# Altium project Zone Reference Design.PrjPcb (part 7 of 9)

## Sheet AM263P Overview.SchDoc
size 431 x 279 mm; Date: Not shown in title block; ApprovedBy: Not shown in title block; CheckedBy: Not shown in title block; Author: Not shown in title block; CompanyName: Not shown in title block; Engineer: Not shown in title block; Organization: Not shown in title block; Address1: Not shown in title block; Address2: Not shown in title block; Address3: Not shown in title block; Address4: Not shown in title block; DocumentNumber: 1; Revision: Use project parameter SCH_Rev; SheetNumber: 6; SheetTotal: 30; PageSetup: Record=PageOptions¦CenterHorizontal=True¦CenterVertical=True¦PrintScale=1.00¦XCorrection=1.00¦YCorrection=1.00¦PrintKind=0¦BorderSize=5000000¦LeftOffset=0¦BottomOffset=0¦Orientation=2¦PaperLength=1000¦PaperWidth=1000¦Scale=100¦PaperSource=15¦PrintQuality=600¦MediaType=1¦DitherType=10¦PaperKind=Letter¦PrintScaleMode=1
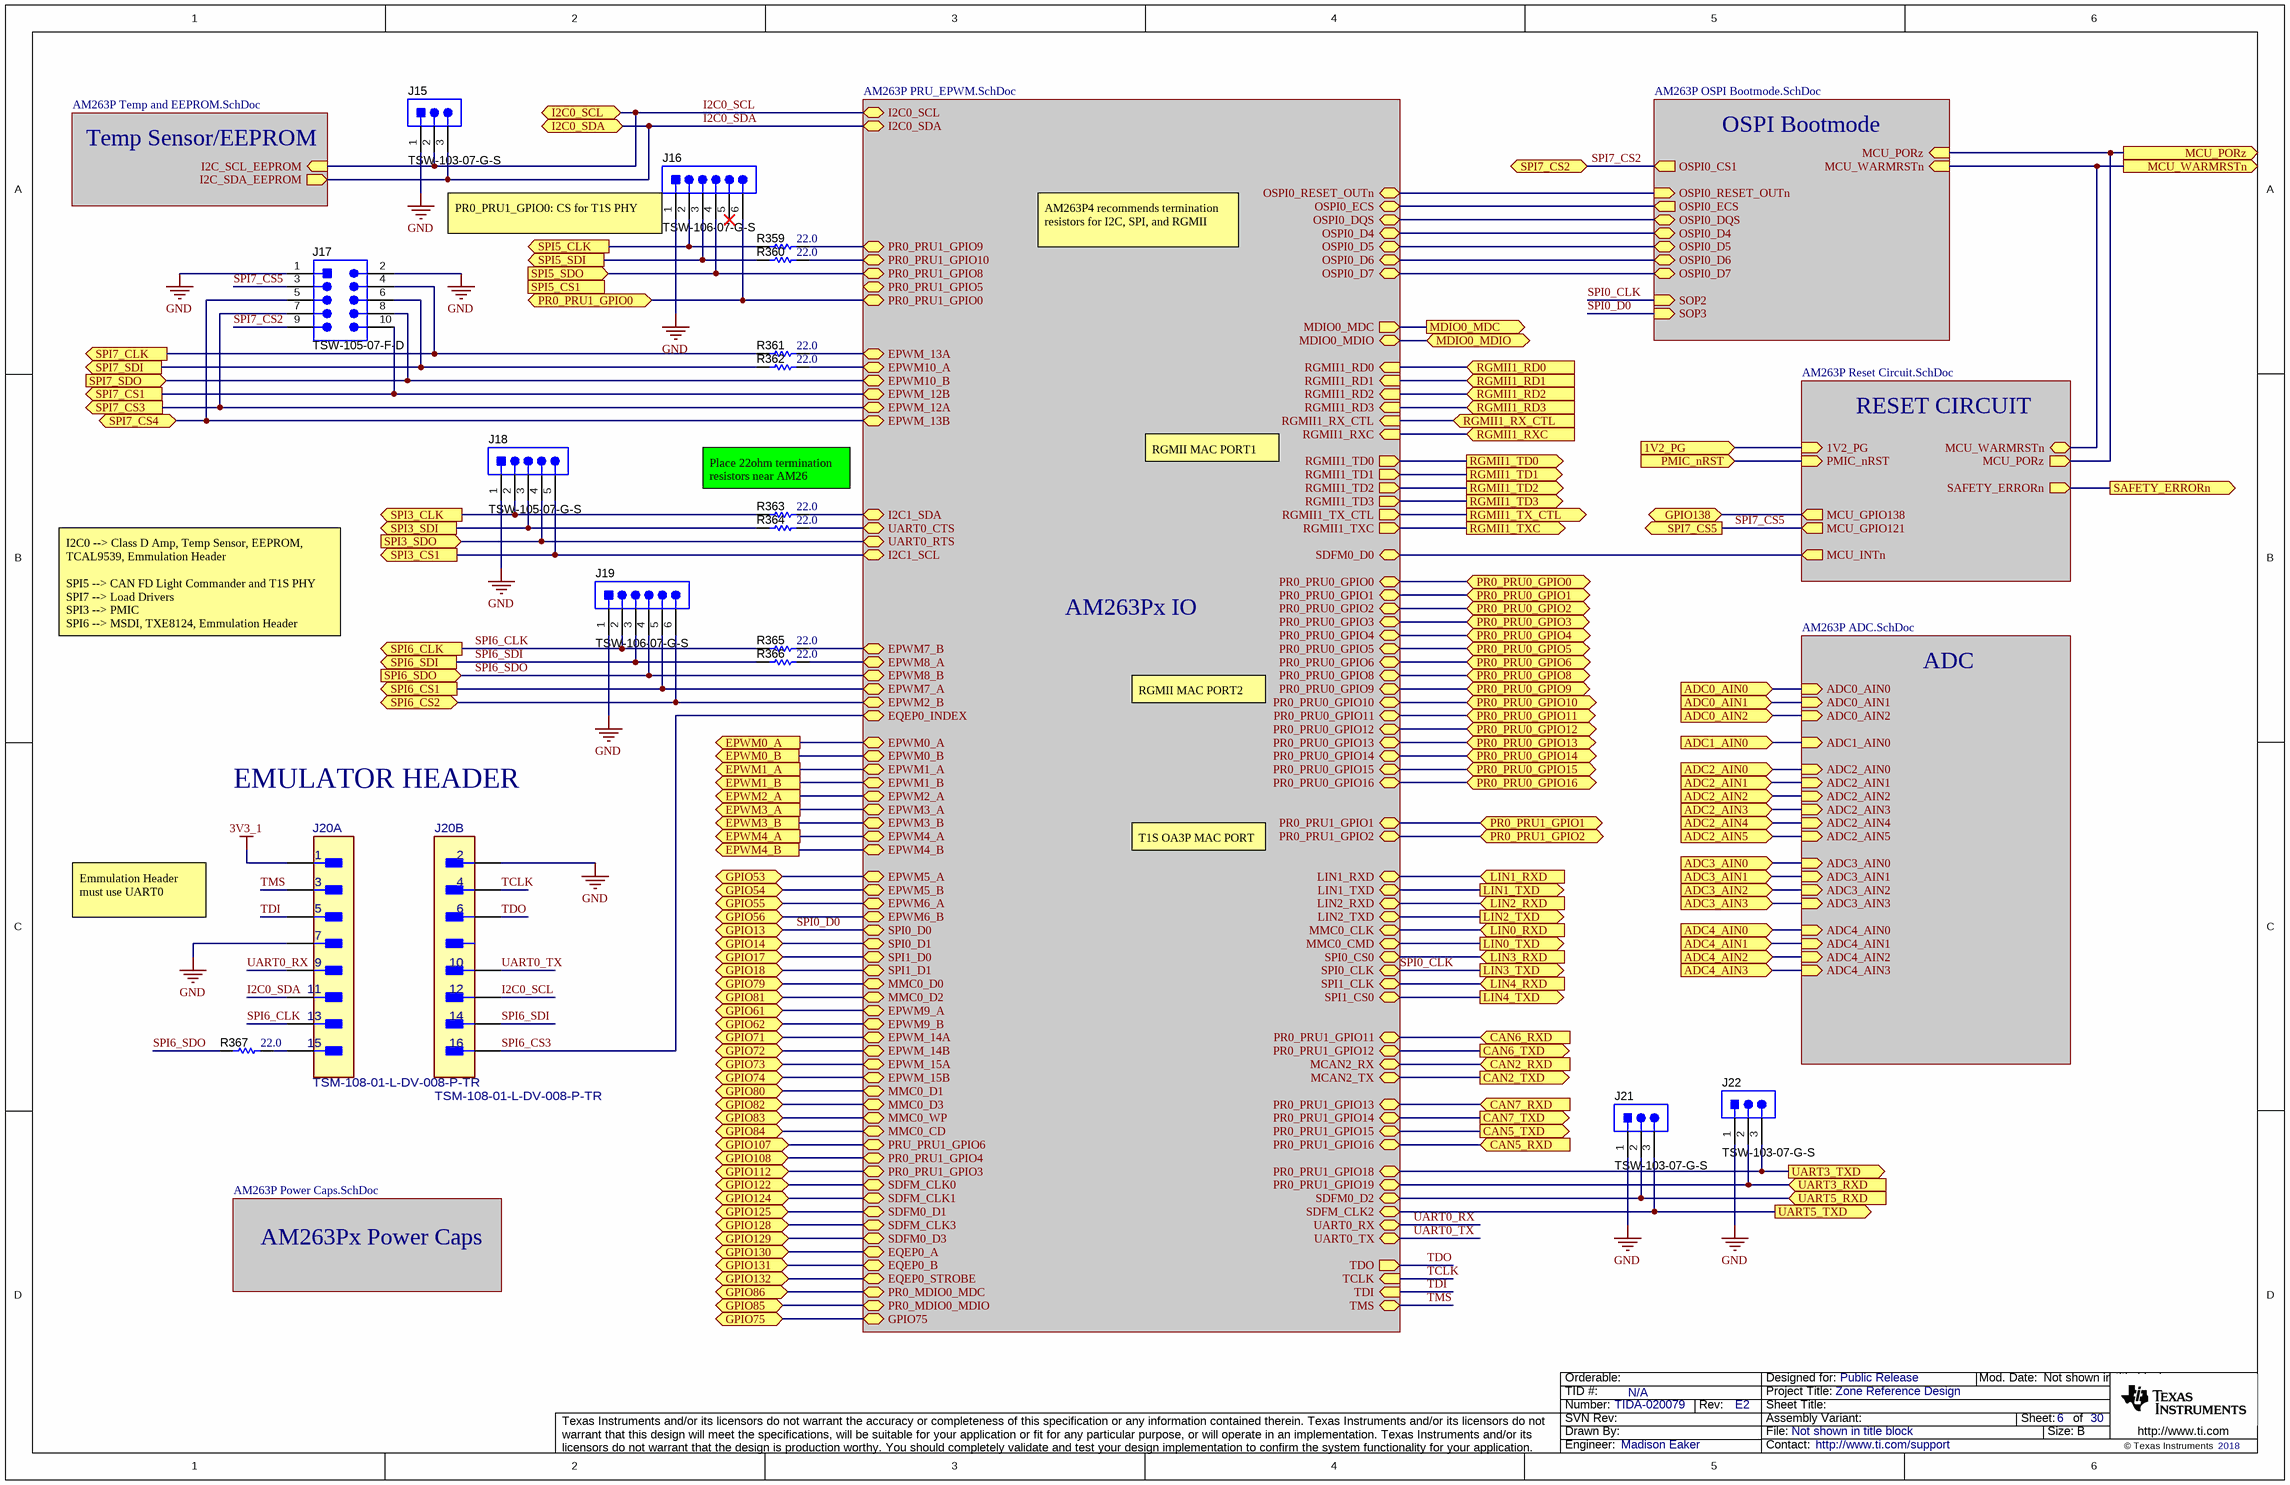
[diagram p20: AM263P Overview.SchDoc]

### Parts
J15  TSW-103-07-G-S  [TSW-103-07-G-S]
J16  TSW-106-07-G-S  [TSW-106-07-G-S]
J17  TSW-105-07-F-D  [Samtec_TSW-105-07-x-D]
J18  TSW-105-07-G-S  [TSW-105-07-X-S]
J19  TSW-106-07-G-S  [TSW-106-07-G-S]
J20  TSM-108-01-L-DV-008-P-TR  [FP-TSM-108-01-L-DV-008-P-TR_HDR15-MFG]  (parts A,B of 2)
J21  TSW-103-07-G-S  [TSW-103-07-G-S]
J22  TSW-103-07-G-S  [TSW-103-07-G-S]
R359  ValueDisplayed: 22.0  [0201]  (hidden comment: RC0201FR-0722RL)
R360  ValueDisplayed: 22.0  [0201]  (hidden comment: RC0201FR-0722RL)
R361  ValueDisplayed: 22.0  [0201]  (hidden comment: RC0201FR-0722RL)
R362  ValueDisplayed: 22.0  [0201]  (hidden comment: RC0201FR-0722RL)
R363  ValueDisplayed: 22.0  [0201]  (hidden comment: RC0201FR-0722RL)
R364  ValueDisplayed: 22.0  [0201]  (hidden comment: RC0201FR-0722RL)
R365  ValueDisplayed: 22.0  [0201]  (hidden comment: RC0201FR-0722RL)
R366  ValueDisplayed: 22.0  [0201]  (hidden comment: RC0201FR-0722RL)
R367  ValueDisplayed: 22.0  [0201]  (hidden comment: RC0201FR-0722RL)

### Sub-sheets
ADC = AM263P ADC.SchDoc: ADC0_AIN0 (in), ADC0_AIN1 (in), ADC1_AIN0 (in), ADC2_AIN0 (in), ADC2_AIN1 (in), ADC2_AIN2 (in), ADC2_AIN3 (in), ADC2_AIN4 (in), ADC2_AIN5 (in), ADC3_AIN0 (in), ADC3_AIN1 (in), ADC3_AIN2 (in), ADC3_AIN3 (in), ADC4_AIN0 (in), ADC4_AIN1 (in), ADC4_AIN2 (in), ADC4_AIN3 (in), ADC0_AIN2 (in)
AM263Px IO = AM263P PRU_EPWM.SchDoc: PR0_PRU0_GPIO0 (bidir), PR0_PRU0_GPIO1 (bidir), PR0_PRU0_GPIO2 (bidir), PR0_PRU0_GPIO3 (bidir), PR0_PRU0_GPIO4 (bidir), PR0_PRU0_GPIO5 (bidir), PR0_PRU0_GPIO6 (bidir), PR0_PRU0_GPIO8 (bidir), PR0_PRU0_GPIO9 (bidir), PR0_PRU0_GPIO10 (bidir), PR0_PRU0_GPIO11 (bidir), PR0_PRU0_GPIO12 (bidir), PR0_PRU0_GPIO13 (bidir), PR0_PRU0_GPIO14 (bidir), PR0_PRU0_GPIO15 (bidir), PR0_PRU0_GPIO16 (bidir), PR0_MDIO0_MDC (bidir), PR0_MDIO0_MDIO (bidir), EPWM0_A (bidir), EPWM0_B (bidir), EPWM1_A (bidir), EPWM1_B (bidir), EPWM2_A (bidir), EPWM2_B (bidir), EPWM3_A (bidir), EPWM3_B (bidir), EPWM4_A (bidir), EPWM4_B (bidir), EPWM5_A (bidir), EPWM5_B (bidir), EPWM6_A (bidir), EPWM6_B (bidir), EPWM7_A (bidir), EPWM7_B (bidir), EPWM8_A (bidir), EPWM8_B (bidir), EPWM9_A (bidir), EPWM9_B (bidir), EPWM10_A (bidir), EPWM10_B (bidir), EPWM_12A (bidir), EPWM_12B (bidir), EPWM_13A (bidir), EPWM_13B (bidir), EQEP0_A (bidir), EQEP0_B (bidir), EQEP0_INDEX (bidir), EQEP0_STROBE (bidir), EPWM_15A (bidir), OSPI0_ECS (bidir), PR0_PRU1_GPIO0 (bidir), PR0_PRU1_GPIO1 (bidir), PR0_PRU1_GPIO2 (bidir), PR0_PRU1_GPIO3 (bidir), PR0_PRU1_GPIO4 (bidir), PR0_PRU1_GPIO5 (bidir), PRU_PRU1_GPIO6 (bidir), PR0_PRU1_GPIO8 (bidir), PR0_PRU1_GPIO9 (bidir), PR0_PRU1_GPIO10 (bidir), PR0_PRU1_GPIO11 (bidir), PR0_PRU1_GPIO12 (bidir), PR0_PRU1_GPIO13 (bidir), PR0_PRU1_GPIO14 (bidir), PR0_PRU1_GPIO15 (bidir), PR0_PRU1_GPIO16 (bidir), PR0_PRU1_GPIO18 (bidir), PR0_PRU1_GPIO19 (bidir), OSPI0_RESET_OUTn (bidir), EPWM_15B (bidir), EPWM_14A (bidir), EPWM_14B (bidir), MDIO0_MDC (out), MDIO0_MDIO (bidir), RGMII1_RD0 (in), RGMII1_RD1 (in), RGMII1_RD2 (in), RGMII1_RD3 (in), RGMII1_RX_CTL (in), RGMII1_RXC (in), RGMII1_TD0 (out), RGMII1_TD1 (out), RGMII1_TD2 (out), RGMII1_TD3 (out), RGMII1_TX_CTL (out), RGMII1_TXC (out), I2C0_SCL (bidir), I2C0_SDA (bidir), UART0_RX (bidir), UART0_TX (bidir), SPI0_CLK (bidir), SPI0_CS0 (bidir), SPI1_CLK (bidir), LIN1_RXD (bidir), LIN1_TXD (bidir), LIN2_RXD (bidir), LIN2_TXD (bidir), SPI1_CS0 (bidir), MCAN2_RX (bidir), MCAN2_TX (bidir), OSPI0_D4 (bidir), OSPI0_D5 (bidir), OSPI0_D6 (bidir), OSPI0_D7 (bidir), GPIO75 (bidir), OSPI0_DQS (bidir), SDFM_CLK0 (bidir), SDFM0_D0 (bidir), SDFM0_D1 (bidir), SDFM0_D2 (bidir), SDFM0_D3 (bidir), SDFM_CLK1 (bidir), SDFM_CLK2 (bidir), SDFM_CLK3 (bidir), TCLK (in), TDI (in), TDO (out), TMS (bidir), MMC0_CD (bidir), MMC0_CLK (bidir), MMC0_CMD (bidir), MMC0_D0 (bidir), MMC0_D1 (bidir), MMC0_D3 (bidir), MMC0_WP (bidir), MMC0_D2 (bidir), I2C1_SCL (bidir), UART0_CTS (bidir), UART0_RTS (bidir), SPI0_D0 (bidir), SPI0_D1 (bidir), SPI1_D0 (bidir), SPI1_D1 (bidir), I2C1_SDA (bidir)
AM263Px Power Caps = AM263P Power Caps.SchDoc: no entries
OSPI Bootmode = AM263P OSPI Bootmode.SchDoc: OSPI0_ECS (out), OSPI0_RESET_OUTn (in), MCU_PORz (in), OSPI0_CS1 (out), MCU_WARMRSTn (in), SOP2 (in), SOP3 (in), OSPI0_D4 (bidir), OSPI0_D5 (bidir), OSPI0_D6 (bidir), OSPI0_D7 (bidir), OSPI0_DQS (bidir)
RESET CIRCUIT = AM263P Reset Circuit.SchDoc: MCU_INTn (out), PMIC_nRST (in), 1V2_PG (in), MCU_PORz (out), SAFETY_ERRORn (out), MCU_GPIO138 (out), MCU_GPIO121 (out), MCU_WARMRSTn (bidir)
Temp Sensor/EEPROM = AM263P Temp and EEPROM.SchDoc: I2C_SDA_EEPROM (out), I2C_SCL_EEPROM (in)

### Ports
1V2_PG (in), ADC0_AIN0 (in), ADC0_AIN1 (in), ADC0_AIN2 (in), ADC1_AIN0 (in), ADC2_AIN0 (in), ADC2_AIN1 (in), ADC2_AIN2 (in), ADC2_AIN3 (in), ADC2_AIN4 (in), ADC2_AIN5 (in), ADC3_AIN0 (in), ADC3_AIN1 (in), ADC3_AIN2 (in), ADC3_AIN3 (in), ADC4_AIN0 (in), ADC4_AIN1 (in), ADC4_AIN2 (in), ADC4_AIN3 (in), CAN2_RXD (in), CAN2_TXD (out), CAN5_RXD (in), CAN5_TXD (out), CAN6_RXD (in), CAN6_TXD (out), CAN7_RXD (in), CAN7_TXD (out), EPWM0_A (out), EPWM0_B (out), EPWM1_A (out), EPWM1_B (out), EPWM2_A (out), EPWM3_A (out), EPWM3_B (out), EPWM4_A (out), EPWM4_B (out), GPIO13 (bidir), GPIO14 (bidir), GPIO17 (bidir), GPIO18 (bidir), GPIO53 (bidir), GPIO54 (bidir), GPIO55 (bidir), GPIO56 (bidir), GPIO61 (bidir), GPIO62 (bidir), GPIO71 (bidir), GPIO72 (bidir), GPIO73 (bidir), GPIO74 (bidir), GPIO75 (bidir), GPIO79 (bidir), GPIO80 (bidir), GPIO81 (bidir), GPIO82 (bidir), GPIO83 (bidir), GPIO84 (bidir), GPIO85 (bidir), GPIO86 (bidir), GPIO107 (bidir), GPIO108 (bidir), GPIO112 (bidir), GPIO122 (bidir), GPIO124 (bidir), GPIO125 (bidir), GPIO128 (bidir), GPIO129 (bidir), GPIO130 (bidir), GPIO131 (bidir), GPIO132 (bidir), GPIO138 (bidir), I2C0_SCL (bidir), I2C0_SDA (bidir), LIN0_RXD (in), LIN0_TXD (out), LIN1_RXD (in), LIN1_TXD (out), LIN2_RXD (in), LIN2_TXD (out), LIN3_RXD (in), LIN3_TXD (out), LIN4_RXD (in), LIN4_TXD (out), MCU_PORz (out), MCU_WARMRSTn (out), MDIO0_MDC (out), MDIO0_MDIO (bidir), PMIC_nRST (in), PR0_PRU0_GPIO0 (bidir), PR0_PRU0_GPIO1 (bidir), PR0_PRU0_GPIO2 (bidir), PR0_PRU0_GPIO3 (bidir), PR0_PRU0_GPIO4 (bidir), PR0_PRU0_GPIO5 (bidir), PR0_PRU0_GPIO6 (bidir), PR0_PRU0_GPIO8 (bidir), PR0_PRU0_GPIO9 (bidir), PR0_PRU0_GPIO10 (bidir), PR0_PRU0_GPIO11 (bidir), PR0_PRU0_GPIO12 (bidir), PR0_PRU0_GPIO13 (bidir), PR0_PRU0_GPIO14 (bidir), PR0_PRU0_GPIO15 (bidir), PR0_PRU0_GPIO16 (bidir), PR0_PRU1_GPIO0 (bidir), PR0_PRU1_GPIO1 (bidir), PR0_PRU1_GPIO2 (bidir), RGMII1_RD0 (in), RGMII1_RD1 (in), RGMII1_RD2 (in), RGMII1_RD3 (in), RGMII1_RX_CTL (in), RGMII1_RXC (in), RGMII1_TD0 (out), RGMII1_TD1 (out), RGMII1_TD2 (out), RGMII1_TD3 (out), RGMII1_TX_CTL (out), RGMII1_TXC (out), SAFETY_ERRORn (out), SPI3_CLK (out), SPI3_CS1 (out), SPI3_SDI (out), SPI3_SDO (in), SPI5_CLK (out), SPI5_CS1 (out), SPI5_SDI (out), SPI5_SDO (in), SPI6_CLK (out), SPI6_CS1 (out), SPI6_CS2 (bidir), SPI6_SDI (out), SPI6_SDO (in), SPI7_CLK (out), SPI7_CS1 (out), SPI7_CS2 (bidir), SPI7_CS3 (out), SPI7_CS4 (bidir), SPI7_CS5 (out), SPI7_SDI (out), SPI7_SDO (in), UART3_RXD (in), UART3_TXD (out), UART5_RXD (in), UART5_TXD (out)

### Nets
3V3_1: J20.1
GND: J15.1 J16.1 J17.1 J17.2 J18.1 J19.1 J20.2 J20.7 J21.1 J22.1
1V2_PG: port 1V2_PG, sheet RESET CIRCUIT/1V2_PG
3V3_AlwaysOn_Monitor_MCU: port ADC0_AIN2, sheet ADC/ADC0_AIN2
A0_TMUX1308: port GPIO80, sheet AM263Px IO/MMC0_D1
A1_TMUX1308: port GPIO82, sheet AM263Px IO/MMC0_D3
A2_TMUX1308: port GPIO83, sheet AM263Px IO/MMC0_WP
ADC0_AIN0: port ADC0_AIN0, sheet ADC/ADC0_AIN0
ADC0_AIN1: port ADC0_AIN1, sheet ADC/ADC0_AIN1
ADC1_AIN0: port ADC1_AIN0, sheet ADC/ADC1_AIN0
ADC2_AIN0: port ADC2_AIN0, sheet ADC/ADC2_AIN0
ADC2_AIN1: port ADC2_AIN1, sheet ADC/ADC2_AIN1
ADC2_AIN2: port ADC2_AIN2, sheet ADC/ADC2_AIN2
ADC2_AIN5: port ADC2_AIN5, sheet ADC/ADC2_AIN5
ADC3_AIN0: port ADC3_AIN0, sheet ADC/ADC3_AIN0
ADC3_AIN1: port ADC3_AIN1, sheet ADC/ADC3_AIN1
ADC3_AIN2: port ADC3_AIN2, sheet ADC/ADC3_AIN2
ADC3_AIN3: port ADC3_AIN3, sheet ADC/ADC3_AIN3
ADC4_AIN0: port ADC4_AIN0, sheet ADC/ADC4_AIN0
ADC4_AIN1: port ADC4_AIN1, sheet ADC/ADC4_AIN1
ADC4_AIN2: port ADC4_AIN2, sheet ADC/ADC4_AIN2
ADC4_AIN3: port ADC4_AIN3, sheet ADC/ADC4_AIN3
BIST_EN_TPS3762: port GPIO128, sheet AM263Px IO/SDFM_CLK3
BIST_TPS3762: port GPIO129, sheet AM263Px IO/SDFM0_D3
CAN2_RXD: port CAN2_RXD, sheet AM263Px IO/MCAN2_RX
CAN2_TXD: port CAN2_TXD, sheet AM263Px IO/MCAN2_TX
CAN5_RXD: port CAN5_RXD, sheet AM263Px IO/PR0_PRU1_GPIO16
CAN5_TXD: port CAN5_TXD, sheet AM263Px IO/PR0_PRU1_GPIO15
CAN6_RXD: port CAN6_RXD, sheet AM263Px IO/PR0_PRU1_GPIO11
CAN6_TXD: port CAN6_TXD, sheet AM263Px IO/PR0_PRU1_GPIO12
CAN7_RXD: port CAN7_RXD, sheet AM263Px IO/PR0_PRU1_GPIO13
CAN7_TXD: port CAN7_TXD, sheet AM263Px IO/PR0_PRU1_GPIO14
ClassD_AMP_SDIN_1: port PR0_PRU0_GPIO10, sheet AM263Px IO/PR0_PRU0_GPIO10
ClassD_AMP_SDOUT_1: port PR0_PRU0_GPIO9, sheet AM263Px IO/PR0_PRU0_GPIO9
CRS_DV/RX_CTRL_ETH1: port RGMII1_RX_CTL, sheet AM263Px IO/RGMII1_RX_CTL
CRS_DV/RX_CTRL_ETH2: port PR0_PRU0_GPIO4, sheet AM263Px IO/PR0_PRU0_GPIO4
CS_IO: J19.6 ; port SPI6_CS2, sheet AM263Px IO/EPWM2_B
CS_IO_1_MCU: J19.5 ; port SPI6_CS1, sheet AM263Px IO/EPWM7_A
CS_LD_1_MCU: J17.10 ; port SPI7_CS1, sheet AM263Px IO/EPWM_12B
CS_LD_4: J17.5 ; port SPI7_CS4, sheet AM263Px IO/EPWM_13B
CS_PMIC_MCU: J18.5 ; port SPI3_CS1, sheet AM263Px IO/I2C1_SCL
DI_HCS_MCU: port GPIO138, sheet RESET CIRCUIT/MCU_GPIO138
EN1_TLIN1024A: port GPIO84, sheet AM263Px IO/MMC0_CD
EN/IN1_DRV8245: port EPWM0_A, sheet AM263Px IO/EPWM0_A
EN_INA186: port GPIO17, sheet AM263Px IO/SPI1_D0
EN_TCAN1043A: port GPIO122, sheet AM263Px IO/SDFM_CLK0
EPWM0_B: port EPWM0_B, sheet AM263Px IO/EPWM0_B
EPWM1_A: port EPWM1_A, sheet AM263Px IO/EPWM1_A
EPWM1_B: port EPWM1_B, sheet AM263Px IO/EPWM1_B
EPWM2_A: port EPWM2_A, sheet AM263Px IO/EPWM2_A
EPWM3_A: port EPWM3_A, sheet AM263Px IO/EPWM3_A
EPWM3_B: port EPWM3_B, sheet AM263Px IO/EPWM3_B
EPWM4_A: port EPWM4_A, sheet AM263Px IO/EPWM4_A
EPWM4_B: port EPWM4_B, sheet AM263Px IO/EPWM4_B
EPWM5_A: port GPIO53, sheet AM263Px IO/EPWM5_A
EPWM5_B: port GPIO54, sheet AM263Px IO/EPWM5_B
EPWM6_A: port GPIO55, sheet AM263Px IO/EPWM6_A
EPWM6_B: port GPIO56, sheet AM263Px IO/EPWM6_B
EPWM7_B: R365.2 ; sheet AM263Px IO/EPWM7_B
EPWM8_A: R366.2 ; sheet AM263Px IO/EPWM8_A
EPWM9_A: port GPIO61, sheet AM263Px IO/EPWM9_A
EPWM9_B: port GPIO62, sheet AM263Px IO/EPWM9_B
EPWM10_A: R362.2 ; sheet AM263Px IO/EPWM10_A
EPWM_13A: R361.2 ; sheet AM263Px IO/EPWM_13A
EPWM_14A: port GPIO71, sheet AM263Px IO/EPWM_14A
EPWM_14B: port GPIO72, sheet AM263Px IO/EPWM_14B
EPWM_15A: port GPIO73, sheet AM263Px IO/EPWM_15A
EQEP0_A: port GPIO130, sheet AM263Px IO/EQEP0_A
EQEP0_B: port GPIO131, sheet AM263Px IO/EQEP0_B
EQEP0_STROBE: port GPIO132, sheet AM263Px IO/EQEP0_STROBE
FG_LM74704_MCU: port GPIO18, sheet AM263Px IO/SPI1_D1
GPIO14: port GPIO14, sheet AM263Px IO/SPI0_D1
GPIO75: port GPIO75, sheet AM263Px IO/GPIO75
GPIO79: port GPIO79, sheet AM263Px IO/MMC0_D0
GPIO81: port GPIO81, sheet AM263Px IO/MMC0_D2
GPIO85: port GPIO85, sheet AM263Px IO/PR0_MDIO0_MDIO
GPIO86: port GPIO86, sheet AM263Px IO/PR0_MDIO0_MDC
GPIO107: port GPIO107, sheet AM263Px IO/PRU_PRU1_GPIO6
GPIO108: port GPIO108, sheet AM263Px IO/PR0_PRU1_GPIO4
GPIO112: port GPIO112, sheet AM263Px IO/PR0_PRU1_GPIO3
GPIO124: port GPIO124, sheet AM263Px IO/SDFM_CLK1
GPIO125: port GPIO125, sheet AM263Px IO/SDFM0_D1
I2C0_SCL: J15.2 J20.12 ; port I2C0_SCL, sheet Temp Sensor/EEPROM/I2C_SCL_EEPROM, sheet AM263Px IO/I2C0_SCL
I2C0_SDA: J15.3 J20.11 ; port I2C0_SDA, sheet Temp Sensor/EEPROM/I2C_SDA_EEPROM, sheet AM263Px IO/I2C0_SDA
I2C1_SDA: R363.2 ; sheet AM263Px IO/I2C1_SDA
I2S_FSYNC_ETH_MCU: port PR0_PRU0_GPIO8, sheet AM263Px IO/PR0_PRU0_GPIO8
I2S_SCLK_ETH_MCU: port PR0_PRU0_GPIO5, sheet AM263Px IO/PR0_PRU0_GPIO5
IMON: port ADC2_AIN3, sheet ADC/ADC2_AIN3
ITMPO: port ADC2_AIN4, sheet ADC/ADC2_AIN4
LIN0_RXD: port LIN0_RXD, sheet AM263Px IO/MMC0_CLK
LIN0_TXD: port LIN0_TXD, sheet AM263Px IO/MMC0_CMD
LIN1_RXD: port LIN1_RXD, sheet AM263Px IO/LIN1_RXD
LIN1_TXD: port LIN1_TXD, sheet AM263Px IO/LIN1_TXD
LIN2_RXD: port LIN2_RXD, sheet AM263Px IO/LIN2_RXD
LIN2_TXD: port LIN2_TXD, sheet AM263Px IO/LIN2_TXD
LIN3_RXD: port LIN3_RXD, sheet AM263Px IO/SPI0_CS0
LIN4_RXD: port LIN4_RXD, sheet AM263Px IO/SPI1_CLK
LIN4_TXD: port LIN4_TXD, sheet AM263Px IO/SPI1_CS0
MCU_INTn: sheet RESET CIRCUIT/MCU_INTn, sheet AM263Px IO/SDFM0_D0
MCU_PORz: port MCU_PORz, sheet RESET CIRCUIT/MCU_PORz, sheet OSPI Bootmode/MCU_PORz
MCU_WARMRSTn: port MCU_WARMRSTn, sheet RESET CIRCUIT/MCU_WARMRSTn, sheet OSPI Bootmode/MCU_WARMRSTn
MDC_ETH: port MDIO0_MDC, sheet AM263Px IO/MDIO0_MDC
MDIO_ETH: port MDIO0_MDIO, sheet AM263Px IO/MDIO0_MDIO
nCS: J17.7 ; port SPI7_CS3, sheet AM263Px IO/EPWM_12A
OA3_ED/SPI_CS_ETH3: J16.6 ; port PR0_PRU1_GPIO0, sheet AM263Px IO/PR0_PRU1_GPIO0
OA3_RX_ETH3: port PR0_PRU1_GPIO1, sheet AM263Px IO/PR0_PRU1_GPIO1
OA3_TX_ETH3: port PR0_PRU1_GPIO2, sheet AM263Px IO/PR0_PRU1_GPIO2
OSPI0_D4: sheet OSPI Bootmode/OSPI0_D4, sheet AM263Px IO/OSPI0_D4
OSPI0_D5: sheet OSPI Bootmode/OSPI0_D5, sheet AM263Px IO/OSPI0_D5
OSPI0_D6: sheet OSPI Bootmode/OSPI0_D6, sheet AM263Px IO/OSPI0_D6
OSPI0_D7: sheet OSPI Bootmode/OSPI0_D7, sheet AM263Px IO/OSPI0_D7
OSPI0_DQS: sheet OSPI Bootmode/OSPI0_DQS, sheet AM263Px IO/OSPI0_DQS
OSPI0_ECS: sheet OSPI Bootmode/OSPI0_ECS, sheet AM263Px IO/OSPI0_ECS
OSPI0_RESET_OUTn: sheet OSPI Bootmode/OSPI0_RESET_OUTn, sheet AM263Px IO/OSPI0_RESET_OUTn
PMIC_nRST: port PMIC_nRST, sheet RESET CIRCUIT/PMIC_nRST
PR0_PRU0_GPIO0: port PR0_PRU0_GPIO0, sheet AM263Px IO/PR0_PRU0_GPIO0
PR0_PRU0_GPIO1: port PR0_PRU0_GPIO1, sheet AM263Px IO/PR0_PRU0_GPIO1
PR0_PRU0_GPIO2: port PR0_PRU0_GPIO2, sheet AM263Px IO/PR0_PRU0_GPIO2
PR0_PRU0_GPIO3: port PR0_PRU0_GPIO3, sheet AM263Px IO/PR0_PRU0_GPIO3
PR0_PRU0_GPIO6: port PR0_PRU0_GPIO6, sheet AM263Px IO/PR0_PRU0_GPIO6
PR0_PRU0_GPIO11: port PR0_PRU0_GPIO11, sheet AM263Px IO/PR0_PRU0_GPIO11
PR0_PRU0_GPIO12: port PR0_PRU0_GPIO12, sheet AM263Px IO/PR0_PRU0_GPIO12
PR0_PRU0_GPIO13: port PR0_PRU0_GPIO13, sheet AM263Px IO/PR0_PRU0_GPIO13
PR0_PRU0_GPIO14: port PR0_PRU0_GPIO14, sheet AM263Px IO/PR0_PRU0_GPIO14
PR0_PRU0_GPIO15: port PR0_PRU0_GPIO15, sheet AM263Px IO/PR0_PRU0_GPIO15
PR0_PRU0_GPIO16: port PR0_PRU0_GPIO16, sheet AM263Px IO/PR0_PRU0_GPIO16
PR0_PRU1_GPIO8: J16.4 ; port SPI5_SDO, sheet AM263Px IO/PR0_PRU1_GPIO8
PR0_PRU1_GPIO9: R359.2 ; sheet AM263Px IO/PR0_PRU1_GPIO9
PR0_PRU1_GPIO10: R360.2 ; sheet AM263Px IO/PR0_PRU1_GPIO10
PR0_PRU1_GPIO18: J22.3 ; port UART3_TXD, sheet AM263Px IO/PR0_PRU1_GPIO18
PR0_PRU1_GPIO19: J22.2 ; port UART3_RXD, sheet AM263Px IO/PR0_PRU1_GPIO19
PWM_ETH: port GPIO74, sheet AM263Px IO/EPWM_15B
RGMII1_RD0: port RGMII1_RD0, sheet AM263Px IO/RGMII1_RD0
RGMII1_RD1: port RGMII1_RD1, sheet AM263Px IO/RGMII1_RD1
RGMII1_RD2: port RGMII1_RD2, sheet AM263Px IO/RGMII1_RD2
RGMII1_RD3: port RGMII1_RD3, sheet AM263Px IO/RGMII1_RD3
RGMII1_RXC: port RGMII1_RXC, sheet AM263Px IO/RGMII1_RXC
RGMII1_TD0: port RGMII1_TD0, sheet AM263Px IO/RGMII1_TD0
RGMII1_TD1: port RGMII1_TD1, sheet AM263Px IO/RGMII1_TD1
RGMII1_TD2: port RGMII1_TD2, sheet AM263Px IO/RGMII1_TD2
RGMII1_TD3: port RGMII1_TD3, sheet AM263Px IO/RGMII1_TD3
RGMII1_TX_CTL: port RGMII1_TX_CTL, sheet AM263Px IO/RGMII1_TX_CTL
RGMII1_TXC: port RGMII1_TXC, sheet AM263Px IO/RGMII1_TXC
RXD2_TCAN1046_UART: J21.2 ; port UART5_RXD, sheet AM263Px IO/SDFM0_D2
SAFETY_ERRORn: port SAFETY_ERRORn, sheet RESET CIRCUIT/SAFETY_ERRORn
SCLK: J17.4 R361.1 ; port SPI7_CLK
SCLK_PMIC: J18.2 R363.1 ; port SPI3_CLK
SDFM_CLK2: J21.3 ; port UART5_TXD, sheet AM263Px IO/SDFM_CLK2
SDI: J17.6 R362.1 ; port SPI7_SDI
SDI_PMIC: J18.3 R364.1 ; port SPI3_SDI
SDO_LD: J17.8 ; port SPI7_SDO, sheet AM263Px IO/EPWM10_B
SDO_PMIC: J18.4 ; port SPI3_SDO, sheet AM263Px IO/UART0_RTS
SPI0_CLK: port LIN3_TXD, sheet OSPI Bootmode/SOP2, sheet AM263Px IO/SPI0_CLK
SPI0_D0: port GPIO13, sheet OSPI Bootmode/SOP3, sheet AM263Px IO/SPI0_D0
SPI5_CLK: J16.2 R359.1 ; port SPI5_CLK
SPI5_SDI: J16.3 R360.1 ; port SPI5_SDI
SPI6_CLK: J19.2 J20.13 R365.1 ; port SPI6_CLK  [project net SCLK_IO]
SPI6_CS3: J20.16 ; sheet AM263Px IO/EQEP0_INDEX
SPI6_SDI: J19.3 J20.14 R366.1 ; port SPI6_SDI  [project net SDI_IO]
SPI6_SDO: J19.4 R367.1 ; port SPI6_SDO, sheet AM263Px IO/EPWM8_B  [project net SDO_IO]
SPI7_CS2: J17.9 ; port SPI7_CS2, sheet OSPI Bootmode/OSPI0_CS1
SPI7_CS5: J17.3 ; port SPI7_CS5, sheet RESET CIRCUIT/MCU_GPIO121
TCLK: J20.4 ; sheet AM263Px IO/TCLK
TDI: J20.5 ; sheet AM263Px IO/TDI
TDO: J20.6 ; sheet AM263Px IO/TDO
TMS: J20.3 ; sheet AM263Px IO/TMS
UART0_CTS: R364.2 ; sheet AM263Px IO/UART0_CTS
UART0_RX: J20.9 ; sheet AM263Px IO/UART0_RX
UART0_TX: J20.10 ; sheet AM263Px IO/UART0_TX
NetJ20_15: J20.15 R367.2

Not connected (* = marked no-connect by the designer): J16 5*

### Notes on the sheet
- (near J16) PR0_PRU1_GPIO0: CS for T1S PHY
- AM263P4 recommends termination resistors for I2C, SPI, and RGMII
- Place 22ohm termination resistors near AM26
- RGMII MAC PORT1
- I2C0 --> Class D Amp, Temp Sensor, EEPROM, TCAL9539, Emmulation Header
  SPI5 --> CAN FD Light Commander and T1S PHY
  SPI7 --> Load Drivers
  SPI3 --> PMIC
  SPI6 --> MSDI, TXE8124, Emmulation Header
- RGMII MAC PORT2
- EMULATOR HEADER
- T1S OA3P MAC PORT
- Emmulation Header must use UART0

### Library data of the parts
J15 J21 J22 = CMP-0075407-2: Header, 100mil, 3x1, Gold, TH; Manufacturer: Samtec; Pitch_mm: 2.54; Cert_VDE: N; Gender: Male; Cert_CSA: Y; Voltage_V: 550V; Green_REACh: Passed; Current_A: 6.3A; Green_Lifecycle: Active; Row_Count: 1
J16 J19 = CMP-0075413-2: Header, 100mil, 6x1, Gold, TH; Manufacturer: Samtec; Pitch_mm: 2.54; Cert_VDE: N; Gender: Male; Cert_CSA: Y; Voltage_V: 550V; Green_REACh: Passed; Current_A: 6.3A; Green_Lifecycle: Active; Row_Count: 1
J17 = CMP-0075665-2: Header, 2.54mm, 5x2, Gold, Black, TH; Manufacturer: Samtec; Pitch_mm: 2.54; Gender: Male; Cert_CSA: Y; Green_REACh: Passed; Shrouded: N; Green_Lifecycle: Active; Row_Count: 2
J18 = CMP-0075411-1: Header, 100mil, 5x1, Gold, TH; Manufacturer: Samtec; Pitch_mm: 2.54; Cert_VDE: N; Gender: Male; Cert_CSA: Y; Voltage_V: 550V; Green_REACh: Passed; Current_A: 6.3A; CT: False; Green_Lifecycle: Active; Row_Count: 1; CNHeader: True
J20 = CMP-0121706-1: Conn Unshrouded HDR 16 POS 2.54mm Solder ST SMT; Manufacturer: Samtec; ContactFinish: Gold,Nickel; Row_Count: 2; AEC Qualified: No; Conn Gender: Male; Conn Orientation: Vertical; SizeZ_mm: 10.16mm; Standoff Height: 1.02mm
R359-R367 = CMP-0027500-1: RES, 22.0, 1%, 0.05 W, 0201; Manufacturer: Yageo America; Power_W: 50mW; TempCo: 200 ppm/C; Value_Code: 22R0; U/M: EA; Value: 22.0; Res_ohm: 22; SizeX_mm: 0.6; SizeY_mm: 0.3; SizeZ_mm: 0.26; Value2: 0.05W; SizeArea_mm2: 0.18; AEC Qualified: N; VDC_V: 25V; AEC Category: Q200

## Sheet AM263P Reset Circuit.SchDoc
size 431 x 279 mm; Date: Not shown in title block; ApprovedBy: Not shown in title block; CheckedBy: Not shown in title block; Author: Not shown in title block; CompanyName: Not shown in title block; Engineer: Not shown in title block; Organization: Not shown in title block; Address1: Not shown in title block; Address2: Not shown in title block; Address3: Not shown in title block; Address4: Not shown in title block; DocumentNumber: 2; Revision: Use project parameter SCH_Rev; SheetNumber: 12; SheetTotal: 30; PageSetup: Record=PageOptions¦CenterHorizontal=True¦CenterVertical=True¦PrintScale=1.00¦XCorrection=1.00¦YCorrection=1.00¦PrintKind=0¦BorderSize=5000000¦LeftOffset=0¦BottomOffset=0¦Orientation=2¦PaperLength=1000¦PaperWidth=1000¦Scale=100¦PaperSource=15¦PrintQuality=600¦MediaType=1¦DitherType=10¦PaperKind=Letter¦PrintScaleMode=1
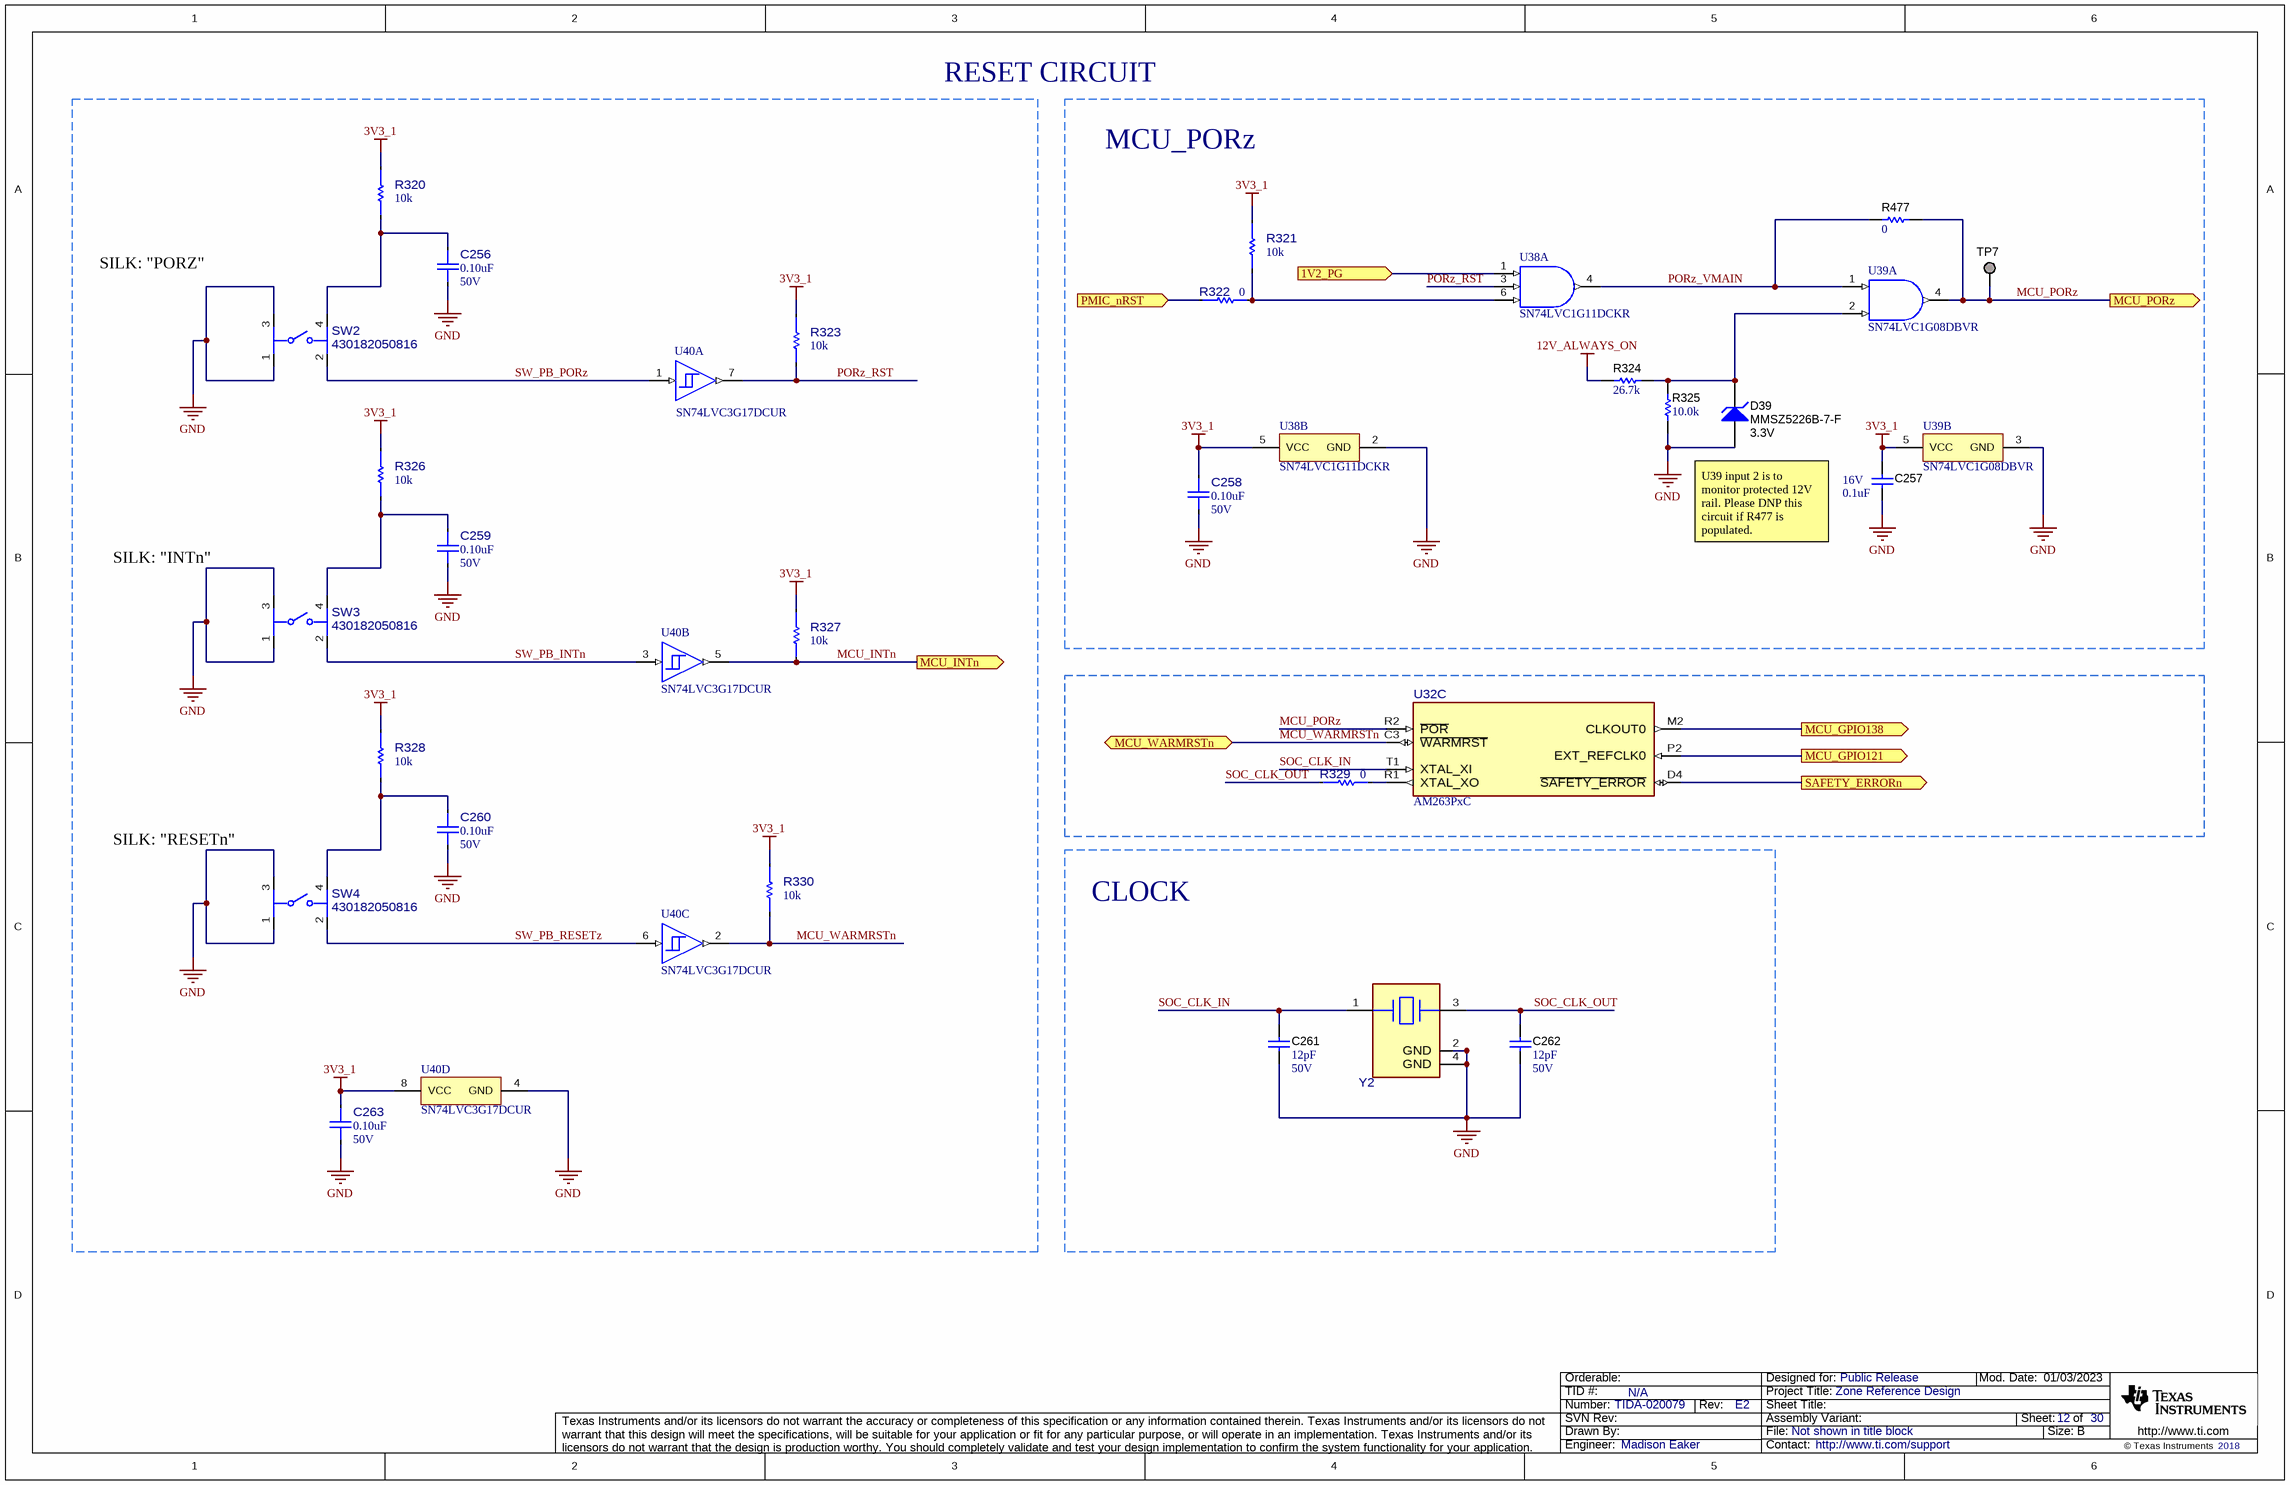
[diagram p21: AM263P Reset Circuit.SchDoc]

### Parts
C256  ValueDisplayed: 0.10uF  VDC_V: 50V  [FP-GRM155R71H104KE14D_0402-MFG]  (hidden comment: GRM155R71H104KE14D)
C257  VDC_V: 16V  ValueDisplayed: 0.1uF  [0201]  (hidden comment: GRM033Z71C104KE14D)
C258  ValueDisplayed: 0.10uF  VDC_V: 50V  [FP-GRM155R71H104KE14D_0402-MFG]  (hidden comment: GRM155R71H104KE14D)
C259  ValueDisplayed: 0.10uF  VDC_V: 50V  [FP-GRM155R71H104KE14D_0402-MFG]  (hidden comment: GRM155R71H104KE14D)
C260  ValueDisplayed: 0.10uF  VDC_V: 50V  [FP-GRM155R71H104KE14D_0402-MFG]  (hidden comment: GRM155R71H104KE14D)
C261  ValueDisplayed: 12pF  VDC_V: 50V  [0402]  (hidden comment: CGA2B2C0G1H120J050BA)
C262  ValueDisplayed: 12pF  VDC_V: 50V  [0402]  (hidden comment: CGA2B2C0G1H120J050BA)
C263  ValueDisplayed: 0.10uF  VDC_V: 50V  [FP-GRM155R71H104KE14D_0402-MFG]  (hidden comment: GRM155R71H104KE14D)
D39  MMSZ5226B-7-F  value 3.3V  [SOD-123]
R320  value 10k  [FP-RC0402JR-0710KL_0402-MFG]  (hidden comment: RC0402JR-0710KL)
R321  value 10k  [FP-RC0402JR-0710KL_0402-MFG]  (hidden comment: RC0402JR-0710KL)
R322  value 0  [FP-ERJ-2GE0R00X_0402-MFG]  (hidden comment: ERJ-2GE0R00X)
R323  value 10k  [FP-RC0402JR-0710KL_0402-MFG]  (hidden comment: RC0402JR-0710KL)
R324  ValueDisplayed: 26.7k  [0603]  (hidden comment: CRCW060326K7FKEA)
R325  ValueDisplayed: 10.0k  [TNPW0603]  (hidden comment: TNPW060310K0BEEA)
R326  value 10k  [FP-RC0402JR-0710KL_0402-MFG]  (hidden comment: RC0402JR-0710KL)
R327  value 10k  [FP-RC0402JR-0710KL_0402-MFG]  (hidden comment: RC0402JR-0710KL)
R328  value 10k  [FP-RC0402JR-0710KL_0402-MFG]  (hidden comment: RC0402JR-0710KL)
R329  value 0  [FP-ERJ-2GE0R00X_0402-MFG]  (hidden comment: ERJ-2GE0R00X)
R330  value 10k  [FP-RC0402JR-0710KL_0402-MFG]  (hidden comment: RC0402JR-0710KL)
R477  ValueDisplayed: 0  [0603]  (hidden comment: CRCW06030000Z0EA)
SW2  430182050816  [FP-430182050816_SMT_SW_6MM2_6MM2-MFG]
SW3  430182050816  [FP-430182050816_SMT_SW_6MM2_6MM2-MFG]
SW4  430182050816  [FP-430182050816_SMT_SW_6MM2_6MM2-MFG]
TP7  TESTPOINT  [TP_25MIL-SMT]  (value not drawn)  (no BOM)
U32  AM263PxC  [ZCZ0324A-MFG]  (part C of 13)
U38  SN74LVC1G11DCKR  [DCK0006A_N]  (parts A,B of 2)
U39  SN74LVC1G08DBVR  [DBV0005A_N]  (parts A,B of 2)
U40  SN74LVC3G17DCUR  [DCU0008A_N]  (parts A,B,C,D of 4)
Y2  ABM10W-25.0000MHZ-8-K1Z-T3  [FP-ABM10W-25.0000MHZ-8-K1Z-T3_SMT4_2MM5_2MM0-MFG]  (value not drawn)

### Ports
1V2_PG (in), MCU_GPIO121 (out), MCU_GPIO138 (out), MCU_INTn (out), MCU_PORz (out), MCU_WARMRSTn (bidir), PMIC_nRST (in), SAFETY_ERRORn (out)

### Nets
3V3_1: C257.1 C258.1 C263.1 R320.1 R321.1 R323.1 R326.1 R327.1 R328.1 R330.1 U38.5(VCC) U39.5(VCC) U40.8(VCC)
12V_ALWAYS_ON: R324.1
GND: C256.2 C257.2 C258.2 C259.2 C260.2 C261.2 C262.1 C263.2 D39.2(A) R325.1 SW2.1 SW2.3 SW3.1 SW3.3 SW4.1 SW4.3 U38.2(GND) U39.3(GND) U40.4(GND) Y2.2(GND) Y2.4(GND)
1V2_PG: U38.1(A) ; port 1V2_PG
DI_HCS_MCU: U32.M2(CLKOUT0) ; port MCU_GPIO138
MCU_INTn: R327.2 U40.5(2Y) ; port MCU_INTn
MCU_PORz: R477.1 TP7.1 U32.R2(~{POR}) U39.4(Y) ; port MCU_PORz
MCU_WARMRSTn: R330.2 U32.C3(~{WARMRST}) U40.2(3Y) ; port MCU_WARMRSTn
PMIC_nRST: R322.1 ; port PMIC_nRST
PORz_RST: R323.2 U38.3(B) U40.7(1Y)  [project net PORz_RST_12]
PORz_VMAIN: R477.2 U38.4(Y) U39.1(A)  [project net PORz_VMAIN_12]
SAFETY_ERRORn: U32.D4(~{SAFETY_ERROR}) ; port SAFETY_ERRORn
SOC_CLK_IN: C261.1 U32.T1(XTAL_XI) Y2.1  [project net SOC_CLK_IN_12]
SOC_CLK_OUT: C262.2 R329.1 Y2.3  [project net SOC_CLK_OUT_12]
SPI7_CS5: U32.P2(EXT_REFCLK0) ; port MCU_GPIO121
SW_PB_INTn: SW3.2 U40.3(2A)  [project net SW_PB_INTn_12]
SW_PB_PORz: SW2.2 U40.1(1A)  [project net SW_PB_PORz_12]
SW_PB_RESETz: SW4.2 U40.6(3A)  [project net SW_PB_RESETz_12]
NetC256_1: C256.1 R320.2 SW2.4
NetC259_1: C259.1 R326.2 SW3.4
NetC260_1: C260.1 R328.2 SW4.4
NetD39_1: D39.1(K) R324.2 R325.2 U39.2(B)
NetR321_2: R321.2 R322.2 U38.6(C)
NetR329_2: R329.2 U32.R1(XTAL_XO)

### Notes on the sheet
- RESET CIRCUIT
- MCU_PORz
- SILK: "PORZ"
- SILK: "INTn"
- U39 input 2 is to
  monitor protected 12V rail. Please DNP this circuit if R477 is populated.
- SILK: "RESETn"
- CLOCK

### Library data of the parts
C256 C258-C260 C263 = CMP-0096855-1: Chip Multilayer Ceramic Capacitors for General Purpose, 0402, 0.10uF, X7R, 15%, 10%, 50V; Manufacturer: Murata; SizeZ_mm: 0.55mm; Value: 100nF; AEC Qualified: No
C257 = CMP-0064970-1: CAP, CERM, 0.1 uF, 16 V,+/- 10%, X7R, 0201; Manufacturer: MuRata; TaMin_C: -55°C; Polarized: N; SizeAreaWB_mm2: 2.08; Value1: Unknown; U/M: EA; Value: 0.1uF; TaMax_C: 125°C; SizeZ_mm: 0.26; SizeX_mm: 0.6; SizeY_mm: 0.3; SizeArea_mm2: 0.18; Cap_F: 100nF; AEC Category: Q200
C261 C262 = CMP-0860828-1: CAP, CERM, 12 pF, 50 V,+/- 5%, C0G/NP0, AEC-Q200 Grade 1, 0402; Manufacturer: TDK; U/M: EA; SizeAreaWB_mm2: 3; AEC Category: Q200; SizeY_mm: 0.5; TaMin_C: -55°C; AEC Grade: 1; TaMax_C: 125°C; Value: 12pF; AEC Qualified: Y; Polarized: N; SizeZ_mm: 0.6
D39 = CMP-0005797-3: Diode, Zener, 3.3 V, 500 mW, SOD-123; Manufacturer: Diodes Inc.; SizeZ_mm: 1.35; SizeX_mm: 3.85; Value1: 0.5W; RJA_CperW: 350; SizeAreaWB_mm2: 13.095; Power_W: 500mW; SizeArea_mm2: 6.545; SizeY_mm: 1.7; AEC Category: Q101
R320 R321 R323 R326-R328 R330 = CMP-0094798-1: Res Thick Film 0402 10K Ohm 5% 0.063W(1/16W) ±100ppm/C Pad SMD T/R; Manufacturer: YAGEO; AEC Qualified: No; Category Cd01000Bfc2916C6: Single Components; SizeZ_mm: 0.4mm; VDC_V: 50V; Category 5C6A91606D4187Ad: Resistors; TempCo: 100ppm/°C; Power_W: 63mW; Category 7542B8484461Ae85: Passive Components
R322 R329 = CMP-0002710-1: 0 Ohms Jumper Chip Resistor 0402 (1005 Metric) Automotive AEC-Q200 Thick Film; Manufacturer: Panasonic; AEC Grade: Grade 0; AEC Qualified: Yes; SizeZ_mm: 0.4mm; Power: 100mW
R324 = CMP-0022249-4: RES, 26.7 k, 1%, 0.1 W, AEC-Q200 Grade 0, 0603; Manufacturer: Vishay-Dale; Power_W: 100mW; TempCo: 100 ppm/C; Value_Code: 26k7; Value: 26.7k; EIA_Code: E96; SizeX_mm: 1.6; SizeY_mm: 0.8; SizeZ_mm: 1; Value2: 0.1W; SizeArea_mm2: 1.28; AEC Qualified: Y; VDC_V: 75V; AEC Category: Q200; AEC Grade: 0
R325 = CMP-0025686-1: RES, 10.0 k, 0.1%, 0.1 W, AEC-Q200 Grade 1, 0603; Manufacturer: Vishay-Dale; Power_W: 100mW; TempCo: 25 ppm/C; Value_Code: 10k0; U/M: EA; Value: 10.0k; EIA_Code: E192; Res_ohm: 10k; SizeX_mm: 1.6; SizeY_mm: 0.85; SizeZ_mm: 0.55; Value2: 0.1W; SizeArea_mm2: 1.36; AEC Qualified: Y; VDC_V: 75V; AEC Grade: 1; AEC Category: Q200
R477 = CMP-0025697-4: RES, 0, 5%, 0.1 W, AEC-Q200 Grade 0, 0603; Manufacturer: Vishay-Dale; Power_W: 100mW; TempCo: 200 ppm/C; Value_Code: 0000; Value: 0; EIA_Code: E24; SizeX_mm: 1.6; SizeY_mm: 0.8; SizeZ_mm: 1; Value2: 0.1W; SizeArea_mm2: 1.28; CompType: Resistor; AEC Qualified: Y; VDC_V: 75V; AEC Category: Q200
SW2-SW4 = CMP-0097324-1: Switch Tactile N.O. SPST Round Button Gull Wing 0.05A 12VDC 1000000Cycles 1.57N SMD Reel; Manufacturer: Wurth Electronics; AEC Qualified: No; Operating Force: 160gf; Coil Resistance_ohm: 100mΩ; VDC_V: 12V; Circuit: SPST-NO; SizeZ_mm: 5.15mm; Contact Current Rating: 50mA
TP7 = CMP-0078143-3: TEST POINT.  No entry in BOM.
U32 = CMP-0001698-2: Sitara™ Microcontroller; Manufacturer: Texas Instruments; SizeZ_mm: 1.4mm; Core Architecture: ARM Cortex-R5F; Data Bus Width: 32bits; Frequency_Fixed: 200MHz; Interface: I2C,SPI,UART,CAN,LIN,Ethernet,Other; Max Supply Voltage: 3.465V; Memory Size: 2MBytes; Memory Type: RAM; Min Supply Voltage: 1.14V; Number Of Cores: 1; Number Of I/Os: 140; Number Of I2C Channels: 4; Number Of Spi Channels: 5; Number Of Uart Channels: 6; Standoff Height: 0.35mm; AEC Category: Q200; CompType: IC
U38 = CMP-0051216-3: Single 3-Input Positive-AND Gate, DCK0006A (SOT-SC70-6); Manufacturer: Texas Instruments; Output Type: CMOS; Bits(#): 1; Input Type: CMOS/TTL; Technology Family: LVC; Schmitt Trigger: No; VCC(Max)(V): 5.5; Gate Type: AND; Rating: Catalog; Output Drive (IOL/IOH)(Max)(mA): 32/-32; ICC @ Nom Voltage(Max)(mA): 0.01; VCC(Min)(V): 1.65; F @ Nom Voltage(Max)(Mhz): 150; Logic: True; Voltage(Nom)(V): 1.8,2.5,3.3,5; tpd @ Nom Voltage(Max)(ns): 20,7.8,6.2,4.6; AEC Category: Q200; AEC Qualified: N; CompType: IC; SizeAreaWB_mm2: 9.3; SizeArea_mm2: 4.2; SizeX_mm: 2.1; SizeY_mm: 2.0; SizeZ_mm: 1.1
U39 = CMP-0051588-2: Single 2-Input Positive-AND Gate, DBV0005A, LARGE T&R; Manufacturer: Texas Instruments; Logic: True; ICC @ Nom Voltage(Max)(mA): 0.01; VCC(Min)(V): 1.65; Bits(#): 1; Rating: Catalog; Schmitt Trigger: No; Voltage(Nom)(V): 1.8,2.5,3.3,5; Output Drive (IOL/IOH)(Max)(mA): 32/-32; Gate Type: AND; tpd @ Nom Voltage(Max)(ns): 4.5,6,4,5; VCC(Max)(V): 5.5; Output Type: CMOS; F @ Nom Voltage(Max)(Mhz): 150; Input Type: CMOS/TTL; Technology Family: LVC; AEC Category: Q200; AEC Qualified: N; CompType: IC
U40 = CMP-0051981-2: TRIPLE SCHMITT-TRIGGER BUFFER, DCU0008A (VSSOP-8); Manufacturer: Texas Instruments; Voltage(Nom)(V): 1.8,2.5,3.3,5; VCC(Max)(V): 5.5; Output Drive (IOL/IOH)(Max)(mA): 32/-32; Output Type: CMOS; tpd @ Nom Voltage(Max)(ns): 9.2,6.2,5.4,4.1; Rating: Catalog; Input Type: CMOS/TTL; 3-State Output: No; Bits(#): 3; Schmitt Trigger: Yes; Logic: True; Technology Family: LVC; F @ Nom Voltage(Max)(Mhz): 150; ICC @ Nom Voltage(Max)(mA): 0.01; VCC(Min)(V): 1.65; AEC Category: Q200; AEC Qualified: N; CompType: IC; SizeAreaWB_mm2: 12.6; SizeArea_mm2: 6.4; SizeX_mm: 3.2; SizeY_mm: 2.0; SizeZ_mm: 0.9
Y2 = CMP-0120101-2: Crystal 25MHz ±10ppm 8pF SMD-4 2.5mm x 2mm; Manufacturer: Abracon; SizeZ_mm: 0.6mm; AEC Qualified: No; Esr: 50Ω; Frequency Stability: 50ppm

## Sheet AM263P Power Caps.SchDoc
size 431 x 279 mm; Date: Not shown in title block; ApprovedBy: Not shown in title block; CheckedBy: Not shown in title block; Author: Not shown in title block; CompanyName: Not shown in title block; Engineer: Not shown in title block; Organization: Not shown in title block; Address1: Not shown in title block; Address2: Not shown in title block; Address3: Not shown in title block; Address4: Not shown in title block; DocumentNumber: 2; Revision: Use project parameter SCH_Rev; SheetNumber: 7; SheetTotal: 30; PageSetup: Record=PageOptions¦CenterHorizontal=True¦CenterVertical=True¦PrintScale=1.00¦XCorrection=1.00¦YCorrection=1.00¦PrintKind=0¦BorderSize=5000000¦LeftOffset=0¦BottomOffset=0¦Orientation=2¦PaperLength=1000¦PaperWidth=1000¦Scale=100¦PaperSource=15¦PrintQuality=600¦MediaType=1¦DitherType=10¦PaperKind=Letter¦PrintScaleMode=1
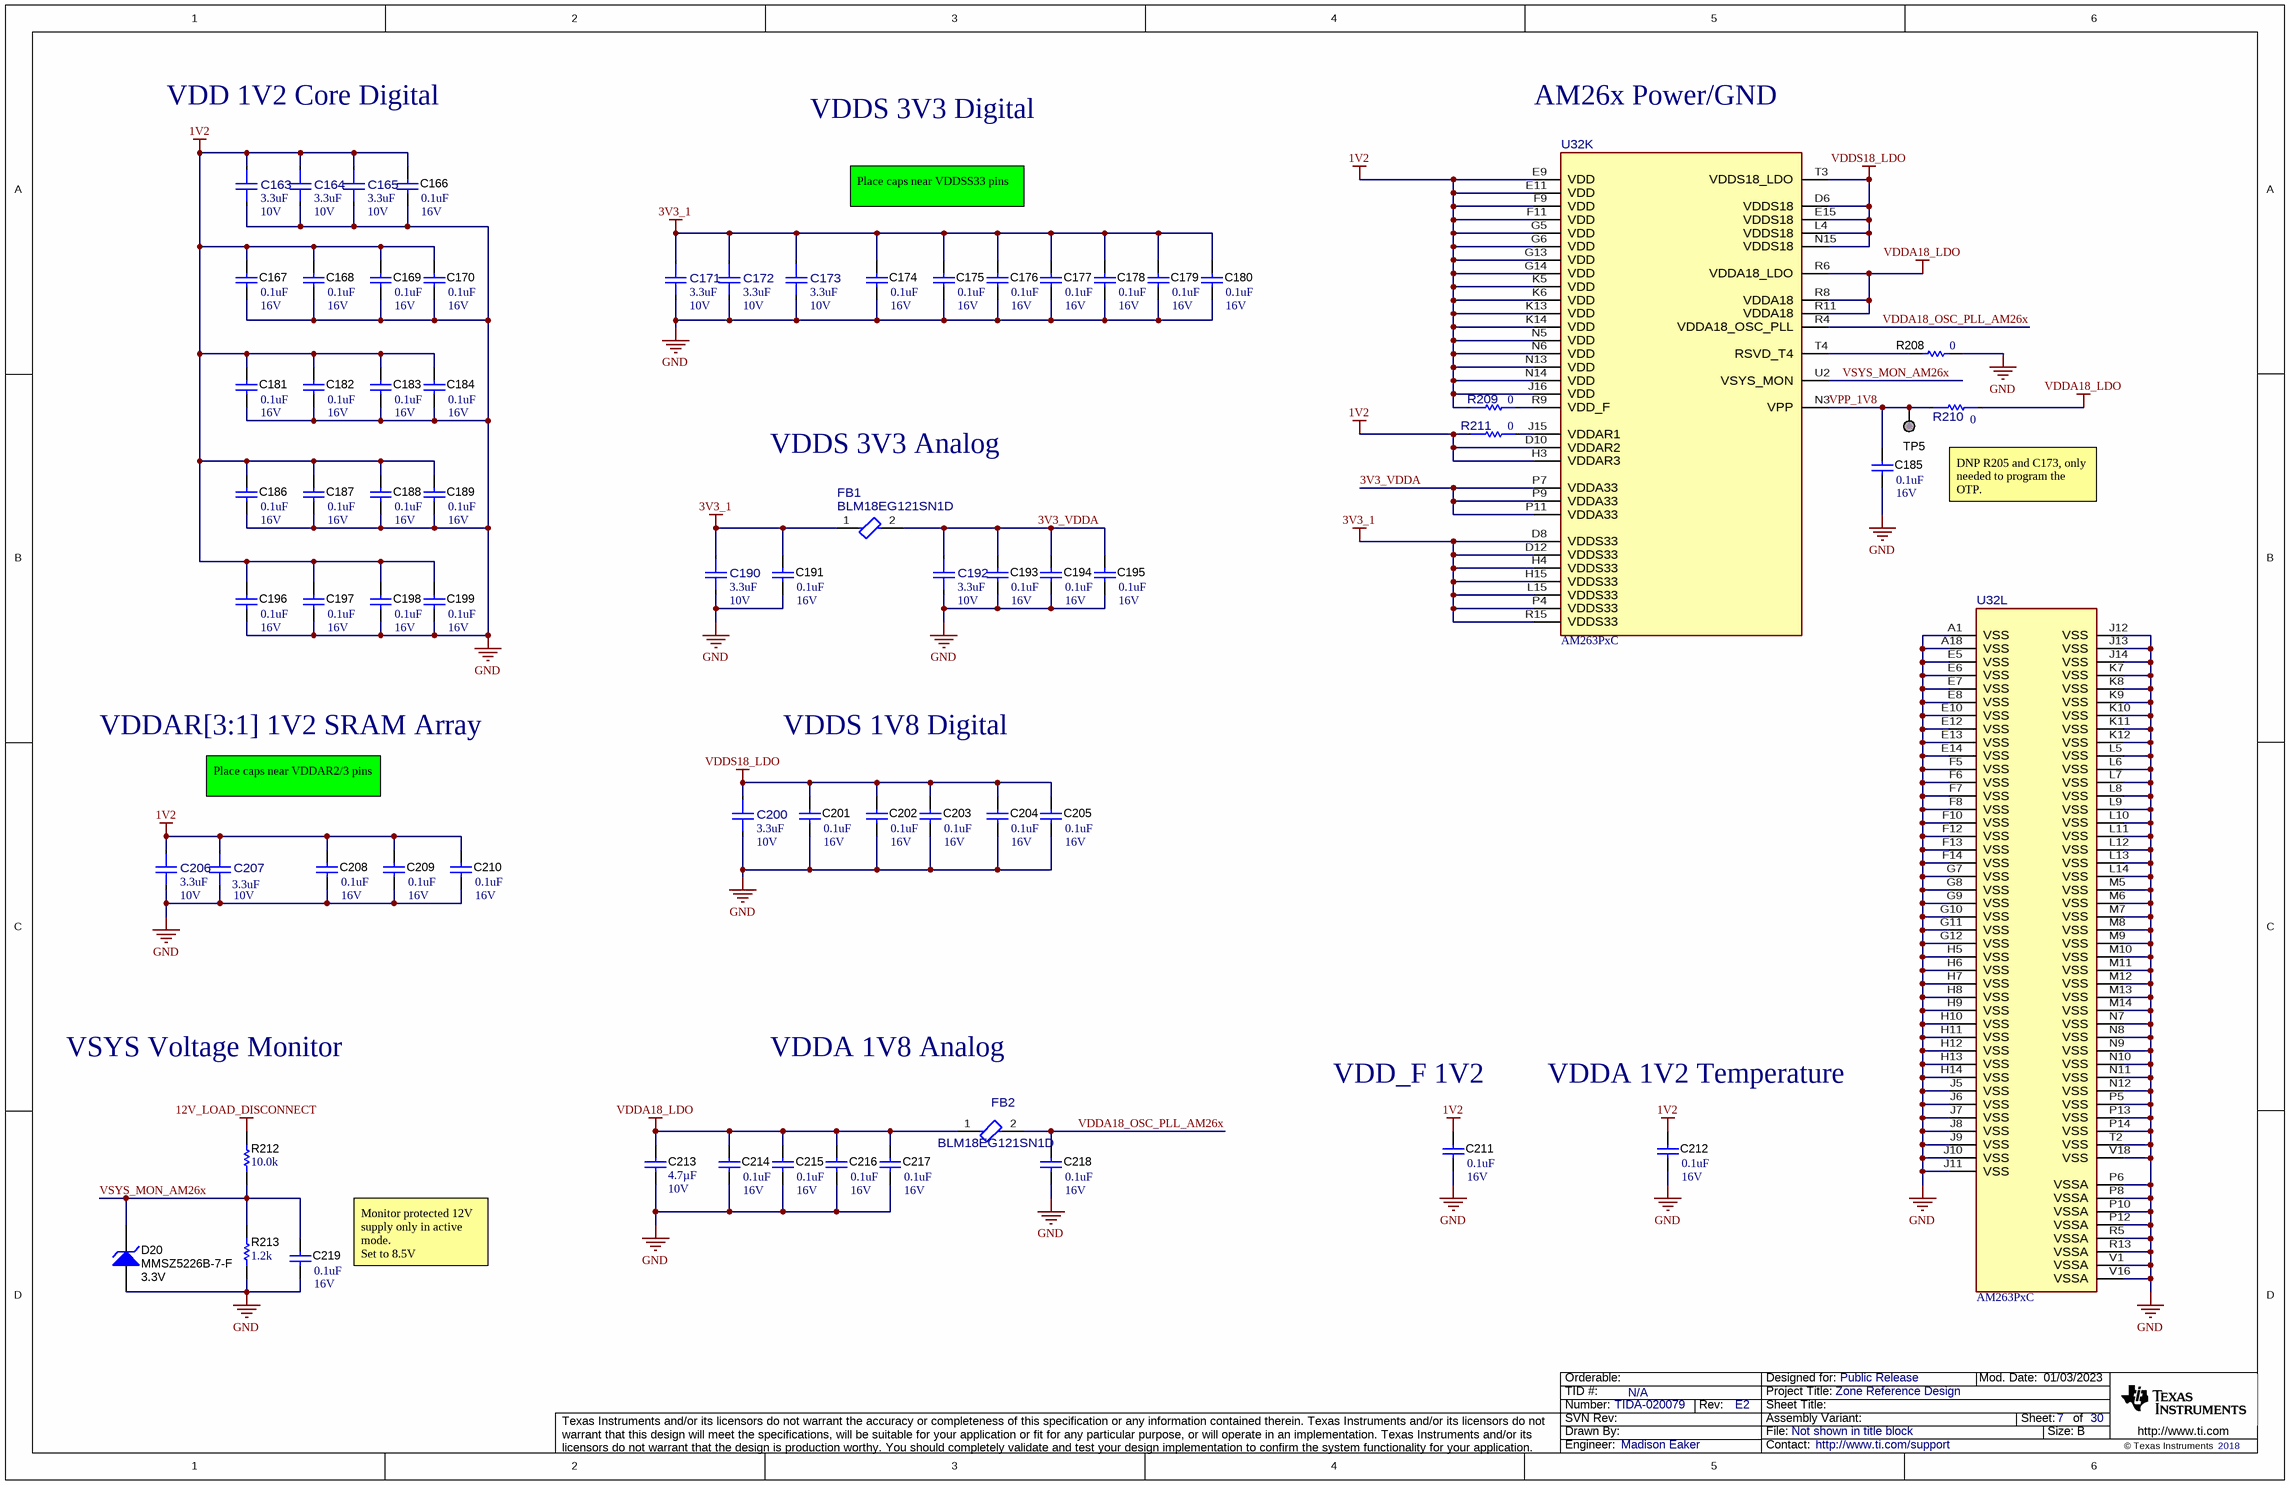
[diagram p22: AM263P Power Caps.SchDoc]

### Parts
C163  ValueDisplayed: 3.3uF  VDC_V: 10V  [FP-CL10A335KP8NNNC_0603-MFG]  (hidden comment: CL10A335KP8NNNC)
C164  ValueDisplayed: 3.3uF  VDC_V: 10V  [FP-CL10A335KP8NNNC_0603-MFG]  (hidden comment: CL10A335KP8NNNC)
C165  ValueDisplayed: 3.3uF  VDC_V: 10V  [FP-CL10A335KP8NNNC_0603-MFG]  (hidden comment: CL10A335KP8NNNC)
C166  VDC_V: 16V  ValueDisplayed: 0.1uF  [0201L]  (hidden comment: GRM033Z71C104KE14D)
C167  VDC_V: 16V  ValueDisplayed: 0.1uF  [0201L]  (hidden comment: GRM033Z71C104KE14D)
C168  VDC_V: 16V  ValueDisplayed: 0.1uF  [0201L]  (hidden comment: GRM033Z71C104KE14D)
C169  VDC_V: 16V  ValueDisplayed: 0.1uF  [0201L]  (hidden comment: GRM033Z71C104KE14D)
C170  VDC_V: 16V  ValueDisplayed: 0.1uF  [0201L]  (hidden comment: GRM033Z71C104KE14D)
C171  ValueDisplayed: 3.3uF  VDC_V: 10V  [FP-CL10A335KP8NNNC_0603-MFG]  (hidden comment: CL10A335KP8NNNC)
C172  ValueDisplayed: 3.3uF  VDC_V: 10V  [FP-CL10A335KP8NNNC_0603-MFG]  (hidden comment: CL10A335KP8NNNC)
C173  ValueDisplayed: 3.3uF  VDC_V: 10V  [FP-CL10A335KP8NNNC_0603-MFG]  (hidden comment: CL10A335KP8NNNC)
C174  VDC_V: 16V  ValueDisplayed: 0.1uF  [0201L]  (hidden comment: GRM033Z71C104KE14D)
C175  VDC_V: 16V  ValueDisplayed: 0.1uF  [0201L]  (hidden comment: GRM033Z71C104KE14D)
C176  VDC_V: 16V  ValueDisplayed: 0.1uF  [0201L]  (hidden comment: GRM033Z71C104KE14D)
C177  VDC_V: 16V  ValueDisplayed: 0.1uF  [0201L]  (hidden comment: GRM033Z71C104KE14D)
C178  VDC_V: 16V  ValueDisplayed: 0.1uF  [0201L]  (hidden comment: GRM033Z71C104KE14D)
C179  VDC_V: 16V  ValueDisplayed: 0.1uF  [0201L]  (hidden comment: GRM033Z71C104KE14D)
C180  VDC_V: 16V  ValueDisplayed: 0.1uF  [0201L]  (hidden comment: GRM033Z71C104KE14D)
C181  VDC_V: 16V  ValueDisplayed: 0.1uF  [0201L]  (hidden comment: GRM033Z71C104KE14D)
C182  VDC_V: 16V  ValueDisplayed: 0.1uF  [0201L]  (hidden comment: GRM033Z71C104KE14D)
C183  VDC_V: 16V  ValueDisplayed: 0.1uF  [0201L]  (hidden comment: GRM033Z71C104KE14D)
C184  VDC_V: 16V  ValueDisplayed: 0.1uF  [0201L]  (hidden comment: GRM033Z71C104KE14D)
C185  VDC_V: 16V  ValueDisplayed: 0.1uF  [0201L]  (hidden comment: GRM033Z71C104KE14D)
C186  VDC_V: 16V  ValueDisplayed: 0.1uF  [0201L]  (hidden comment: GRM033Z71C104KE14D)
C187  VDC_V: 16V  ValueDisplayed: 0.1uF  [0201L]  (hidden comment: GRM033Z71C104KE14D)
C188  VDC_V: 16V  ValueDisplayed: 0.1uF  [0201L]  (hidden comment: GRM033Z71C104KE14D)
C189  VDC_V: 16V  ValueDisplayed: 0.1uF  [0201L]  (hidden comment: GRM033Z71C104KE14D)
C190  ValueDisplayed: 3.3uF  VDC_V: 10V  [FP-CL10A335KP8NNNC_0603-MFG]  (hidden comment: CL10A335KP8NNNC)
C191  VDC_V: 16V  ValueDisplayed: 0.1uF  [0201L]  (hidden comment: GRM033Z71C104KE14D)
C192  ValueDisplayed: 3.3uF  VDC_V: 10V  [FP-CL10A335KP8NNNC_0603-MFG]  (hidden comment: CL10A335KP8NNNC)
C193  VDC_V: 16V  ValueDisplayed: 0.1uF  [0201L]  (hidden comment: GRM033Z71C104KE14D)
C194  VDC_V: 16V  ValueDisplayed: 0.1uF  [0201L]  (hidden comment: GRM033Z71C104KE14D)
C195  VDC_V: 16V  ValueDisplayed: 0.1uF  [0201L]  (hidden comment: GRM033Z71C104KE14D)
C196  VDC_V: 16V  ValueDisplayed: 0.1uF  [0201L]  (hidden comment: GRM033Z71C104KE14D)
C197  VDC_V: 16V  ValueDisplayed: 0.1uF  [0201L]  (hidden comment: GRM033Z71C104KE14D)
C198  VDC_V: 16V  ValueDisplayed: 0.1uF  [0201L]  (hidden comment: GRM033Z71C104KE14D)
C199  VDC_V: 16V  ValueDisplayed: 0.1uF  [0201L]  (hidden comment: GRM033Z71C104KE14D)
C200  ValueDisplayed: 3.3uF  VDC_V: 10V  [FP-CL10A335KP8NNNC_0603-MFG]  (hidden comment: CL10A335KP8NNNC)
C201  VDC_V: 16V  ValueDisplayed: 0.1uF  [0201L]  (hidden comment: GRM033Z71C104KE14D)
C202  VDC_V: 16V  ValueDisplayed: 0.1uF  [0201L]  (hidden comment: GRM033Z71C104KE14D)
C203  VDC_V: 16V  ValueDisplayed: 0.1uF  [0201L]  (hidden comment: GRM033Z71C104KE14D)
C204  VDC_V: 16V  ValueDisplayed: 0.1uF  [0201L]  (hidden comment: GRM033Z71C104KE14D)
C205  VDC_V: 16V  ValueDisplayed: 0.1uF  [0201L]  (hidden comment: GRM033Z71C104KE14D)
C206  VDC_V: 10V  ValueDisplayed: 3.3uF  [FP-CL10A335KP8NNNC_0603-MFG]  (hidden comment: CL10A335KP8NNNC)
C207  VDC_V: 10V  ValueDisplayed: 3.3uF  [FP-CL10A335KP8NNNC_0603-MFG]  (hidden comment: CL10A335KP8NNNC)
C208  VDC_V: 16V  ValueDisplayed: 0.1uF  [0201L]  (hidden comment: GRM033Z71C104KE14D)
C209  VDC_V: 16V  ValueDisplayed: 0.1uF  [0201L]  (hidden comment: GRM033Z71C104KE14D)
C210  VDC_V: 16V  ValueDisplayed: 0.1uF  [0201L]  (hidden comment: GRM033Z71C104KE14D)
C211  VDC_V: 16V  ValueDisplayed: 0.1uF  [0201L]  (hidden comment: GRM033Z71C104KE14D)
C212  VDC_V: 16V  ValueDisplayed: 0.1uF  [0201L]  (hidden comment: GRM033Z71C104KE14D)
C213  Cap_F: 4.7µF  VDC_V: 10V  [0402L]  (hidden comment: GRM155R61A475MEAAD)
C214  VDC_V: 16V  ValueDisplayed: 0.1uF  [0201L]  (hidden comment: GRM033Z71C104KE14D)
C215  VDC_V: 16V  ValueDisplayed: 0.1uF  [0201L]  (hidden comment: GRM033Z71C104KE14D)
C216  VDC_V: 16V  ValueDisplayed: 0.1uF  [0201L]  (hidden comment: GRM033Z71C104KE14D)
C217  VDC_V: 16V  ValueDisplayed: 0.1uF  [0201L]  (hidden comment: GRM033Z71C104KE14D)
C218  VDC_V: 16V  ValueDisplayed: 0.1uF  [0201L]  (hidden comment: GRM033Z71C104KE14D)
C219  VDC_V: 16V  ValueDisplayed: 0.1uF  [0201L]  (hidden comment: GRM033Z71C104KE14D)
D20  MMSZ5226B-7-F  value 3.3V  [SOD-123]
FB1  BLM18EG121SN1D  [FP-BLM18EG121SN1D_0603-MFG]
FB2  BLM18EG121SN1D  [FP-BLM18EG121SN1D_0603-MFG]
R208  ValueDisplayed: 0  [0201]  (hidden comment: ERJ-1GN0R00C)
R209  value 0  [FP-ERJ-2GE0R00X_0402-MFG]  (hidden comment: ERJ-2GE0R00X)
R210  value 0  [FP-ERJ-2GE0R00X_0402-MFG]  (hidden comment: ERJ-2GE0R00X)
R211  value 0  [FP-ERJ-2GE0R00X_0402-MFG]  (hidden comment: ERJ-2GE0R00X)
R212  ValueDisplayed: 10.0k  [TNPW0603]  (hidden comment: TNPW060310K0BEEA)
R213  ValueDisplayed: 1.2k  [0603]  (hidden comment: ERJ-3GEYJ122V)
TP5  TESTPOINT  [TP_25MIL-SMT]  (value not drawn)  (no BOM)
U32  AM263PxC  [ZCZ0324A-MFG]  (parts K,L of 13)

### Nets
1V2: C163.1 C164.1 C165.1 C166.1 C167.1 C168.1 C169.1 C170.1 C181.1 C182.1 C183.1 C184.1 C186.1 C187.1 C188.1 C189.1 C196.1 C197.1 C198.1 C199.1 C206.1 C207.1 C208.1 C209.1 C210.1 C211.1 C212.1 R209.1 R211.1 U32.D10(VDDAR2) U32.E9(VDD) U32.E11(VDD) U32.F9(VDD) U32.F11(VDD) U32.G5(VDD) U32.G6(VDD) U32.G13(VDD) U32.G14(VDD) U32.H3(VDDAR3) U32.J16(VDD) U32.K5(VDD) U32.K6(VDD) U32.K13(VDD) U32.K14(VDD) U32.N5(VDD) U32.N6(VDD) U32.N13(VDD) U32.N14(VDD)
3V3_1: C171.1 C172.1 C173.1 C174.1 C175.1 C176.1 C177.1 C178.1 C179.1 C180.1 C190.1 C191.1 FB1.1 U32.D8(VDDS33) U32.D12(VDDS33) U32.H4(VDDS33) U32.H15(VDDS33) U32.L15(VDDS33) U32.P4(VDDS33) U32.R15(VDDS33)
12V_LOAD_DISCONNECT: R212.2  [project net VS]
GND: C163.2 C164.2 C165.2 C166.2 C167.2 C168.2 C169.2 C170.2 C171.2 C172.2 C173.2 C174.2 C175.2 C176.2 C177.2 C178.2 C179.2 C180.2 C181.2 C182.2 C183.2 C184.2 C185.2 C186.2 C187.2 C188.2 C189.2 C190.2 C191.2 C192.2 C193.2 C194.2 C195.2 C196.2 C197.2 C198.2 C199.2 C200.2 C201.2 C202.2 C203.2 C204.2 C205.2 C206.2 C207.2 C208.2 C209.2 C210.2 C211.2 C212.2 C213.2 C214.2 C215.2 C216.2 C217.2 C218.2 C219.2 D20.2(A) R208.2 R213.1 U32.A1(VSS) U32.A18(VSS) U32.E5(VSS) U32.E6(VSS) U32.E7(VSS) U32.E8(VSS) U32.E10(VSS) U32.E12(VSS) U32.E13(VSS) U32.E14(VSS) U32.F5(VSS) U32.F6(VSS) U32.F7(VSS) U32.F8(VSS) U32.F10(VSS) U32.F12(VSS) U32.F13(VSS) U32.F14(VSS) U32.G7(VSS) U32.G8(VSS) U32.G9(VSS) U32.G10(VSS) U32.G11(VSS) U32.G12(VSS) U32.H5(VSS) U32.H6(VSS) U32.H7(VSS) U32.H8(VSS) U32.H9(VSS) U32.H10(VSS) U32.H11(VSS) U32.H12(VSS) U32.H13(VSS) U32.H14(VSS) U32.J5(VSS) U32.J6(VSS) U32.J7(VSS) U32.J8(VSS) U32.J9(VSS) U32.J10(VSS) U32.J11(VSS) U32.J12(VSS) U32.J13(VSS) U32.J14(VSS) U32.K7(VSS) U32.K8(VSS) U32.K9(VSS) U32.K10(VSS) U32.K11(VSS) U32.K12(VSS) U32.L5(VSS) U32.L6(VSS) U32.L7(VSS) U32.L8(VSS) U32.L9(VSS) U32.L10(VSS) U32.L11(VSS) U32.L12(VSS) U32.L13(VSS) U32.L14(VSS) U32.M5(VSS) U32.M6(VSS) U32.M7(VSS) U32.M8(VSS) U32.M9(VSS) U32.M10(VSS) U32.M11(VSS) U32.M12(VSS) U32.M13(VSS) U32.M14(VSS) U32.N7(VSS) U32.N8(VSS) U32.N9(VSS) U32.N10(VSS) U32.N11(VSS) U32.N12(VSS) U32.P5(VSS) U32.P6(VSSA) U32.P8(VSSA) U32.P10(VSSA) U32.P12(VSSA) U32.P13(VSS) U32.P14(VSS) U32.R5(VSSA) U32.R13(VSSA) U32.T2(VSS) U32.V1(VSSA) U32.V16(VSSA) U32.V18(VSS)
VDDA18_LDO: C213.1 C214.1 C215.1 C216.1 C217.1 FB2.1 R210.2 U32.R6(VDDA18_LDO) U32.R8(VDDA18) U32.R11(VDDA18)
VDDS18_LDO: C200.1 C201.1 C202.1 C203.1 C204.1 C205.1 U32.D6(VDDS18) U32.E15(VDDS18) U32.L4(VDDS18) U32.N15(VDDS18) U32.T3(VDDS18_LDO)
3V3_VDDA: C192.1 C193.1 C194.1 C195.1 FB1.2 U32.P7(VDDA33) U32.P9(VDDA33) U32.P11(VDDA33)  [project net 3V3_VDDA_7]
VDDA18_OSC_PLL_AM26x: C218.1 FB2.2 U32.R4(VDDA18_OSC_PLL)  [project net VDDA18_OSC_PLL_AM26x_7]
VPP_1V8: C185.1 R210.1 TP5.1 U32.N3(VPP)  [project net VPP_1V8_7]
VSYS_MON_AM26x: C219.1 D20.1(K) R212.1 R213.2 U32.U2(VSYS_MON)  [project net VSYS_MON_AM26x_7]
NetR208_1: R208.1 U32.T4(RSVD_T4)
NetR209_2: R209.2 U32.R9(VDD_F)
NetR211_2: R211.2 U32.J15(VDDAR1)

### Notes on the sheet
- VDD 1V2 Core Digital
- VDDS 3V3 Digital
- AM26x Power/GND
- Place caps near VDDSS33 pins
- VDDS 3V3 Analog
- DNP R205 and C173, only needed to program the OTP.
- VDDAR[3:1] 1V2 SRAM Array
- VDDS 1V8 Digital
- Place caps near VDDAR2/3 pins
- VSYS Voltage Monitor
- VDDA 1V8 Analog
- VDD_F 1V2
- VDDA 1V2 Temperature
- Monitor protected 12V supply only in active mode.
  Set to 8.5V

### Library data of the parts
C163-C165 C171-C173 C190 C192 C200 = CMP-0042976-1: Cap Ceramic 3.3uF 10V X5R ±10% Pad SMD 0603 +85°C T/R; Manufacturer: Samsung; AEC Qualified: No; Cap_F: 3.3µF; SizeZ_mm: 0.9mm; TempCo: 15%; Value: 3.3µF
C166-C170 C174-C189 C191 C193-C199 C201-C205 C208-C212 C214-C219 = CMP-0064970-1: CAP, CERM, 0.1 uF, 16 V,+/- 10%, X7R, 0201; Manufacturer: MuRata; TaMin_C: -55°C; Polarized: N; SizeAreaWB_mm2: 2.08; Value1: Unknown; U/M: EA; Value: 0.1uF; TaMax_C: 125°C; SizeZ_mm: 0.26; SizeX_mm: 0.6; SizeY_mm: 0.3; Cap_Case: 0201; SizeArea_mm2: 0.18; Cap_F: 100nF; AEC Category: Q200
C206 C207 = CMP-0042976-1: Cap Ceramic 3.3uF 10V X5R ±10% Pad SMD 0603 +85°C T/R; Manufacturer: Samsung; TempCo: 15%; Value: 3.3µF; SizeZ_mm: 0.9mm; AEC Qualified: No
C213 = CMP-0006582-2: CAP, CERM, 4.7 uF, 10 V, +/- 20%, X5R, 0402; Manufacturer: MuRata; TaMin_C: -55°C; Polarized: N; SizeAreaWB_mm2: 3; Value1: Unknown; U/M: EA; Value: 4.7uF; TaMax_C: 85°C; SizeZ_mm: 0.6; SizeX_mm: 1; SizeY_mm: 0.5; Cap_Case: 0402; AEC Category: Q200
D20 = CMP-0005797-3: as D39 on sheet AM263P Reset Circuit
FB1 FB2 = CMP-0089199-1: 120 Ohms @ 100MHz 1  Ferrite Bead 0603 (1608 Metric) 2A 40mOhm; Manufacturer: Murata; DCR_ohm: 60m; AEC Qualified: No; Tolerance_%: 25%; SizeZ_mm: 0.95mm; Impedance At Frequency: 120Ω @ 100MHz
R208 = CMP-0065361-1: RES, 0, 5%, .05 W, AEC-Q200 Grade 0, 0201; Manufacturer: Panasonic; Power_W: 50mW; Green_Lifecycle: Not Set; TempCo: ppm/C; Value_Code: 0000; Green_REACh: Incomplete; U/M: EA; Value: 0; EIA_Code: E24; SizeX_mm: 0.6; SizeY_mm: 0.3; SizeZ_mm: 0.26; Value2: .05W; SizeArea_mm2: 0.18; AEC Qualified: Y; AEC Category: Q200
R209 R211 = CMP-0002710-1: 0 Ohms Jumper Chip Resistor 0402 (1005 Metric) Automotive AEC-Q200 Thick Film; Manufacturer: Panasonic; SizeZ_mm: 0.4mm; AEC Qualified: Yes; AEC Grade: Grade 0; Power: 100mW
R210 = CMP-0002710-1: as R322 on sheet AM263P Reset Circuit
R212 = CMP-0025686-1: as R325 on sheet AM263P Reset Circuit
R213 = CMP-0025876-1: RES, 1.2 k, 5%, 0.1 W, AEC-Q200 Grade 0, 0603; Manufacturer: Panasonic; Power_W: 100mW; TempCo: 200 ppm/C; Value_Code: 1k20; U/M: EA; Value: 1.2k; EIA_Code: E24; SizeX_mm: 1.6; SizeY_mm: 0.8; SizeZ_mm: 1; Value2: 0.1W; SizeArea_mm2: 1.28; AEC Qualified: Y; VDC_V: 75V; AEC Grade: 0; AEC Category: Q200
TP5 = CMP-0078143-3: TEST POINT.  No entry in BOM.
U32 = CMP-0001698-2: as U32 on sheet AM263P Reset Circuit

## Sheet AM263P Temp and EEPROM.SchDoc
size 431 x 279 mm; Date: Not shown in title block; ApprovedBy: Not shown in title block; CheckedBy: Not shown in title block; Author: Not shown in title block; CompanyName: Not shown in title block; Engineer: Not shown in title block; Organization: Not shown in title block; Address1: Not shown in title block; Address2: Not shown in title block; Address3: Not shown in title block; Address4: Not shown in title block; DocumentNumber: 2; Revision: Use project parameter SCH_Rev; SheetNumber: 11; SheetTotal: 30; PageSetup: Record=PageOptions¦CenterHorizontal=True¦CenterVertical=True¦PrintScale=1.00¦XCorrection=1.00¦YCorrection=1.00¦PrintKind=0¦BorderSize=5000000¦LeftOffset=0¦BottomOffset=0¦Orientation=2¦PaperLength=1000¦PaperWidth=1000¦Scale=100¦PaperSource=15¦PrintQuality=600¦MediaType=1¦DitherType=10¦PaperKind=Letter¦PrintScaleMode=1
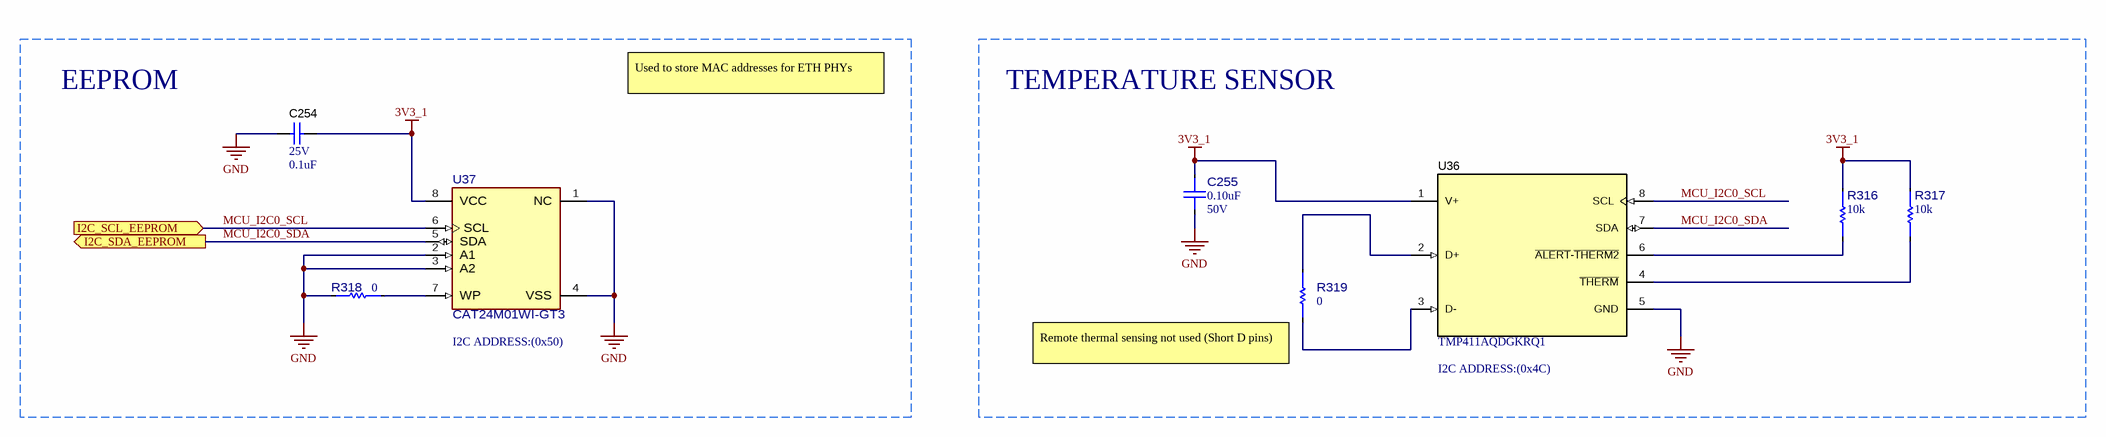
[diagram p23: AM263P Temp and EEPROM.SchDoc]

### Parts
C254  VDC_V: 25V  ValueDisplayed: 0.1uF  [0402]  (hidden comment: GRM155R71E104KE14D)
C255  ValueDisplayed: 0.10uF  VDC_V: 50V  [FP-GRM155R71H104KE14D_0402-MFG]  (hidden comment: GRM155R71H104KE14D)
R316  value 10k  [FP-RC0402JR-0710KL_0402-MFG]  (hidden comment: RC0402JR-0710KL)
R317  value 10k  [FP-RC0402JR-0710KL_0402-MFG]  (hidden comment: RC0402JR-0710KL)
R318  value 0  [FP-ERJ-2GE0R00X_0402-MFG]  (hidden comment: ERJ-2GE0R00X)
R319  value 0  [FP-ERJ-2GE0R00X_0402-MFG]  (hidden comment: ERJ-2GE0R00X)
U36  TMP411AQDGKRQ1  [DGK0008A_N]
U37  CAT24M01WI-GT3  [FP-CAT24M01WI-GT3_SOIC8-IPC_C]

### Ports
I2C_SCL_EEPROM (in), I2C_SDA_EEPROM (out)

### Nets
3V3_1: C254.1 C255.1 R316.1 R317.1 U36.1(V+) U37.8(VCC)
GND: C254.2 C255.2 R318.2 U36.5(GND) U37.1(NC) U37.2(A1) U37.3(A2) U37.4(VSS)
MCU_I2C0_SCL: U36.8(SCL) U37.6(SCL) ; port I2C_SCL_EEPROM  [project net I2C0_SCL]
MCU_I2C0_SDA: U36.7(SDA) U37.5(SDA) ; port I2C_SDA_EEPROM  [project net I2C0_SDA]
NetR316_2: R316.2 U36.6(~{ALERT}-~{THERM2})
NetR317_2: R317.2 U36.4(~{THERM})
NetR318_1: R318.1 U37.7(WP)
NetR319_1: R319.1 U36.2(D+)
NetR319_2: R319.2 U36.3(D-)

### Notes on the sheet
- EEPROM
- Used to store MAC addresses for ETH PHYs
- TEMPERATURE SENSOR
- (near U37) I2C ADDRESS:(0x50)
- (near R319) Remote thermal sensing not used (Short D pins)
- I2C ADDRESS:(0x4C)

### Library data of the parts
C254 = CMP-0006659-2: CAP, CERM, 0.1 uF, 25 V, +/- 10%, X7R, 0402; Manufacturer: MuRata; TaMin_C: -55°C; Polarized: N; SizeAreaWB_mm2: 3; Value1: Unknown; U/M: EA; Value: 0.1uF; TaMax_C: 125°C; SizeZ_mm: 0.6; SizeX_mm: 1; SizeY_mm: 0.5; Cap_F: 100nF; AEC Category: Q200
C255 = CMP-0096855-1: as C256 on sheet AM263P Reset Circuit
R316 R317 = CMP-0094798-1: as R320 on sheet AM263P Reset Circuit
R318 R319 = CMP-0002710-1: as R209 on sheet AM263P Power Caps
U36 = CMP-0860146-1: Automotive Grade, Remote and Local Temperature Sensor with N-Factor and Series-R Correction, DGK0008A (VSSOP-8); Alternate Manufacturer: Texas Instruments; SizeAreaWB_mm2: 23.6; SizeArea_mm2: 14.7; SizeX_mm: 4.9; AEC Category: Q200; SizeZ_mm: 1.1; CompType: IC; AEC Qualified: Y; SizeY_mm: 3
U37 = CMP-0122130-1: EEPROM Serial-I2C 1M-bit 128K x 8 2.5V/3.3V/5V 8-Pin SOIC N T/R; Manufacturer: ON Semi; SizeZ_mm: 1.75mm; Access Time: 0.4us; AEC Qualified: No; Frequency_Fixed: 1MHz; Interface: I2C; Max Supply Voltage: 5.5V; Memory Size: 1Mbits; Min Supply Voltage: 1.8V; Nominal Supply Current: 1-5mA; Standoff Height: 0.1mm; TaMax_C: +85°C; TaMin_C: -40°C; TJmax_C: +150°C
